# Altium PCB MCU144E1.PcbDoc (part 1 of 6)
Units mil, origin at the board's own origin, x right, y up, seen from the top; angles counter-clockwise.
Board outline 2755.9 x 2276.49 mil, 10 copper layers (Top Layer, L02_GND1, L03_SIG1, L04_GND2, L05_SIG2, L06_PWR, L07_GND3, L08_SIG3, L09_GND4, Bottom Layer), stack 60.4 mil thick; 257 components, 312 nets, 1297 pads, 831 vias.
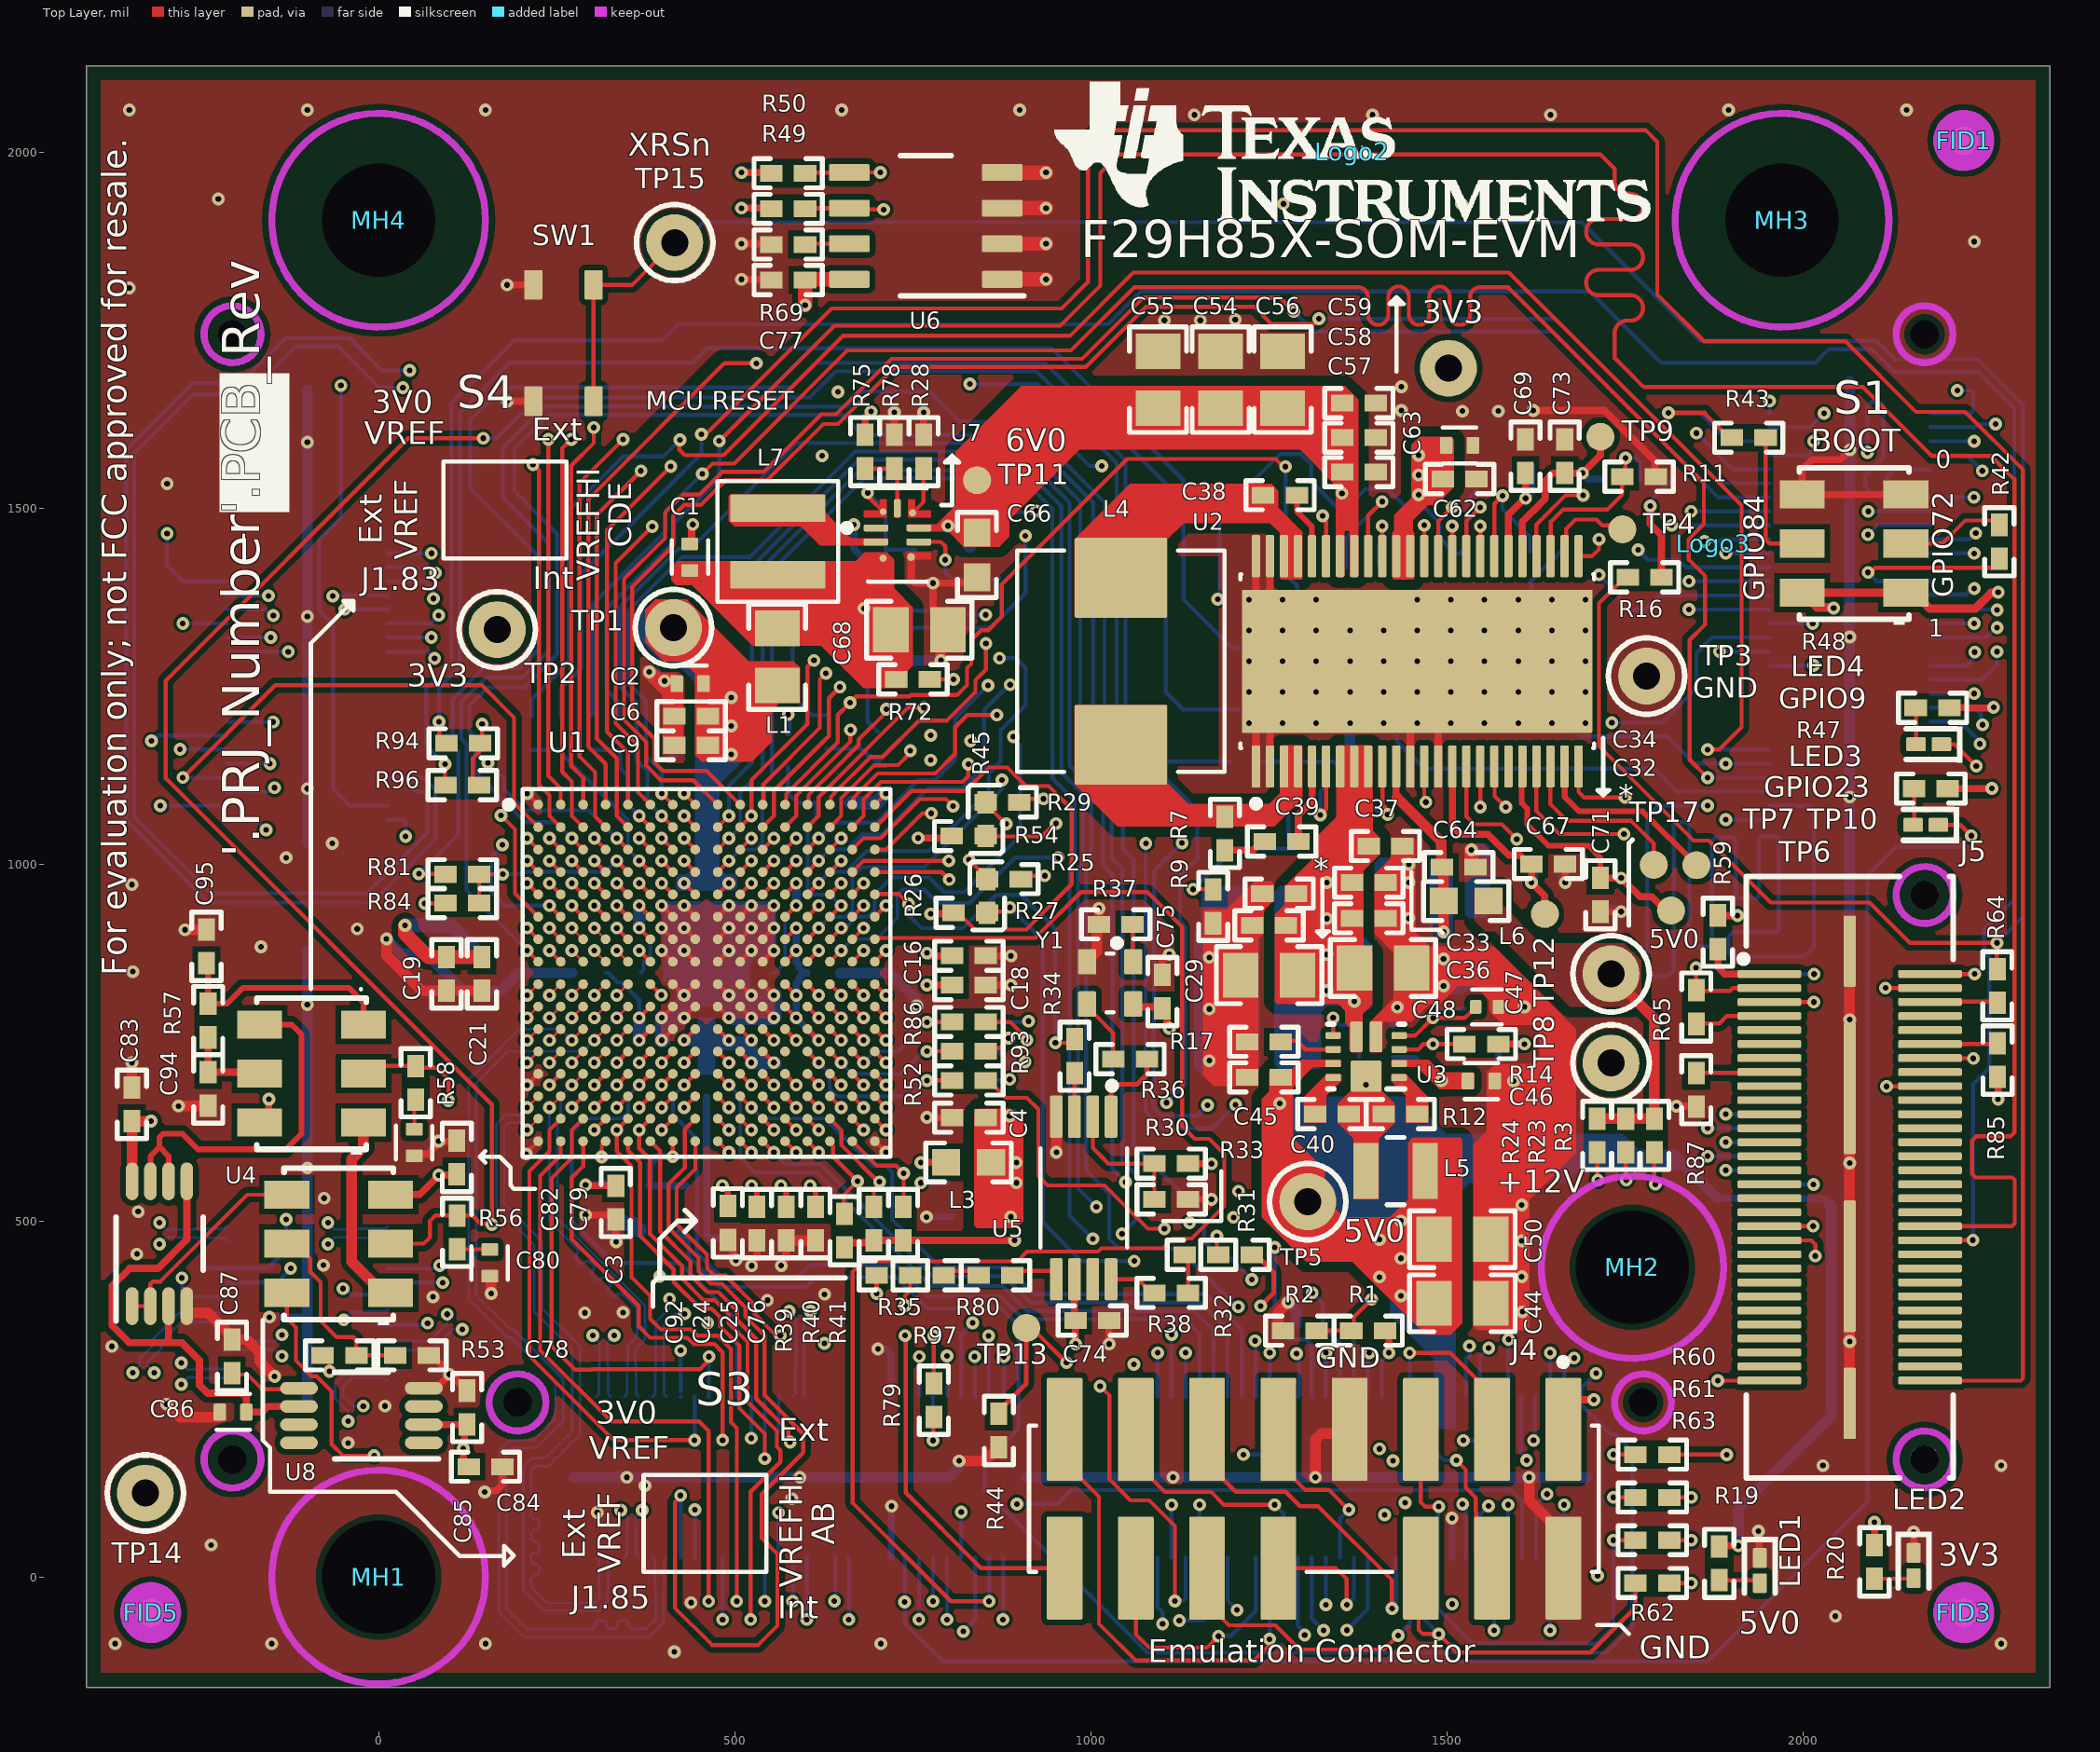
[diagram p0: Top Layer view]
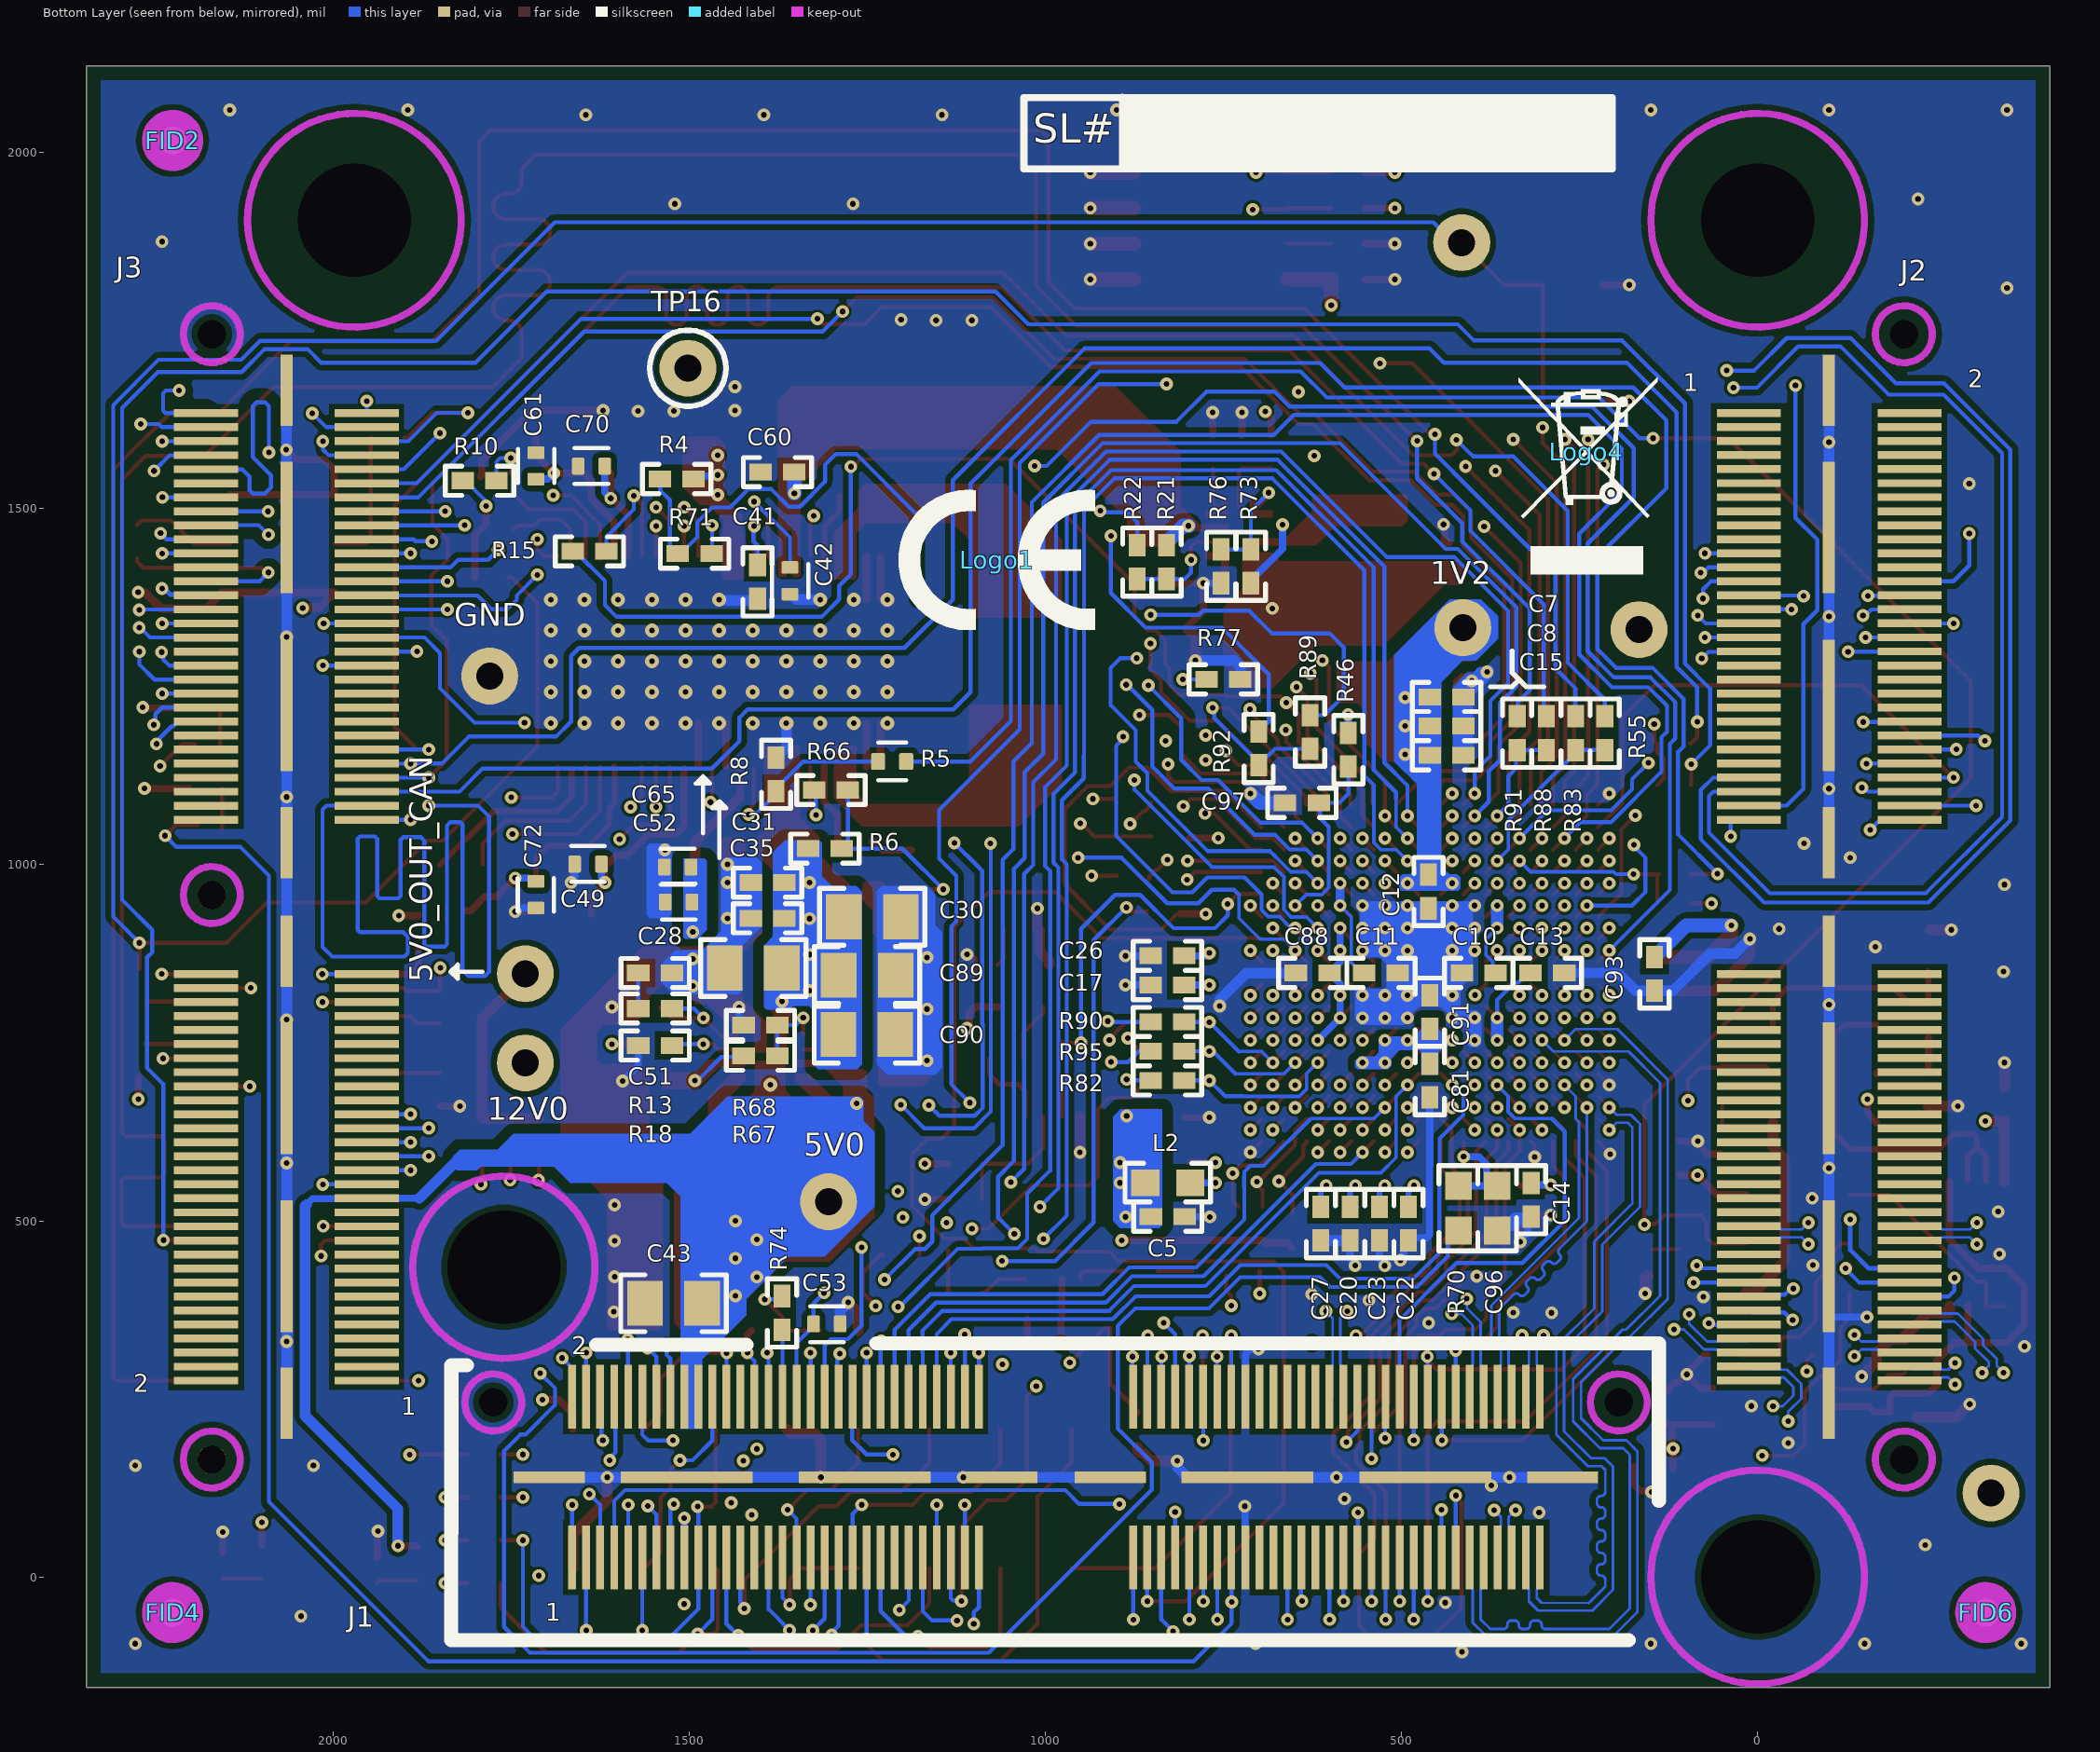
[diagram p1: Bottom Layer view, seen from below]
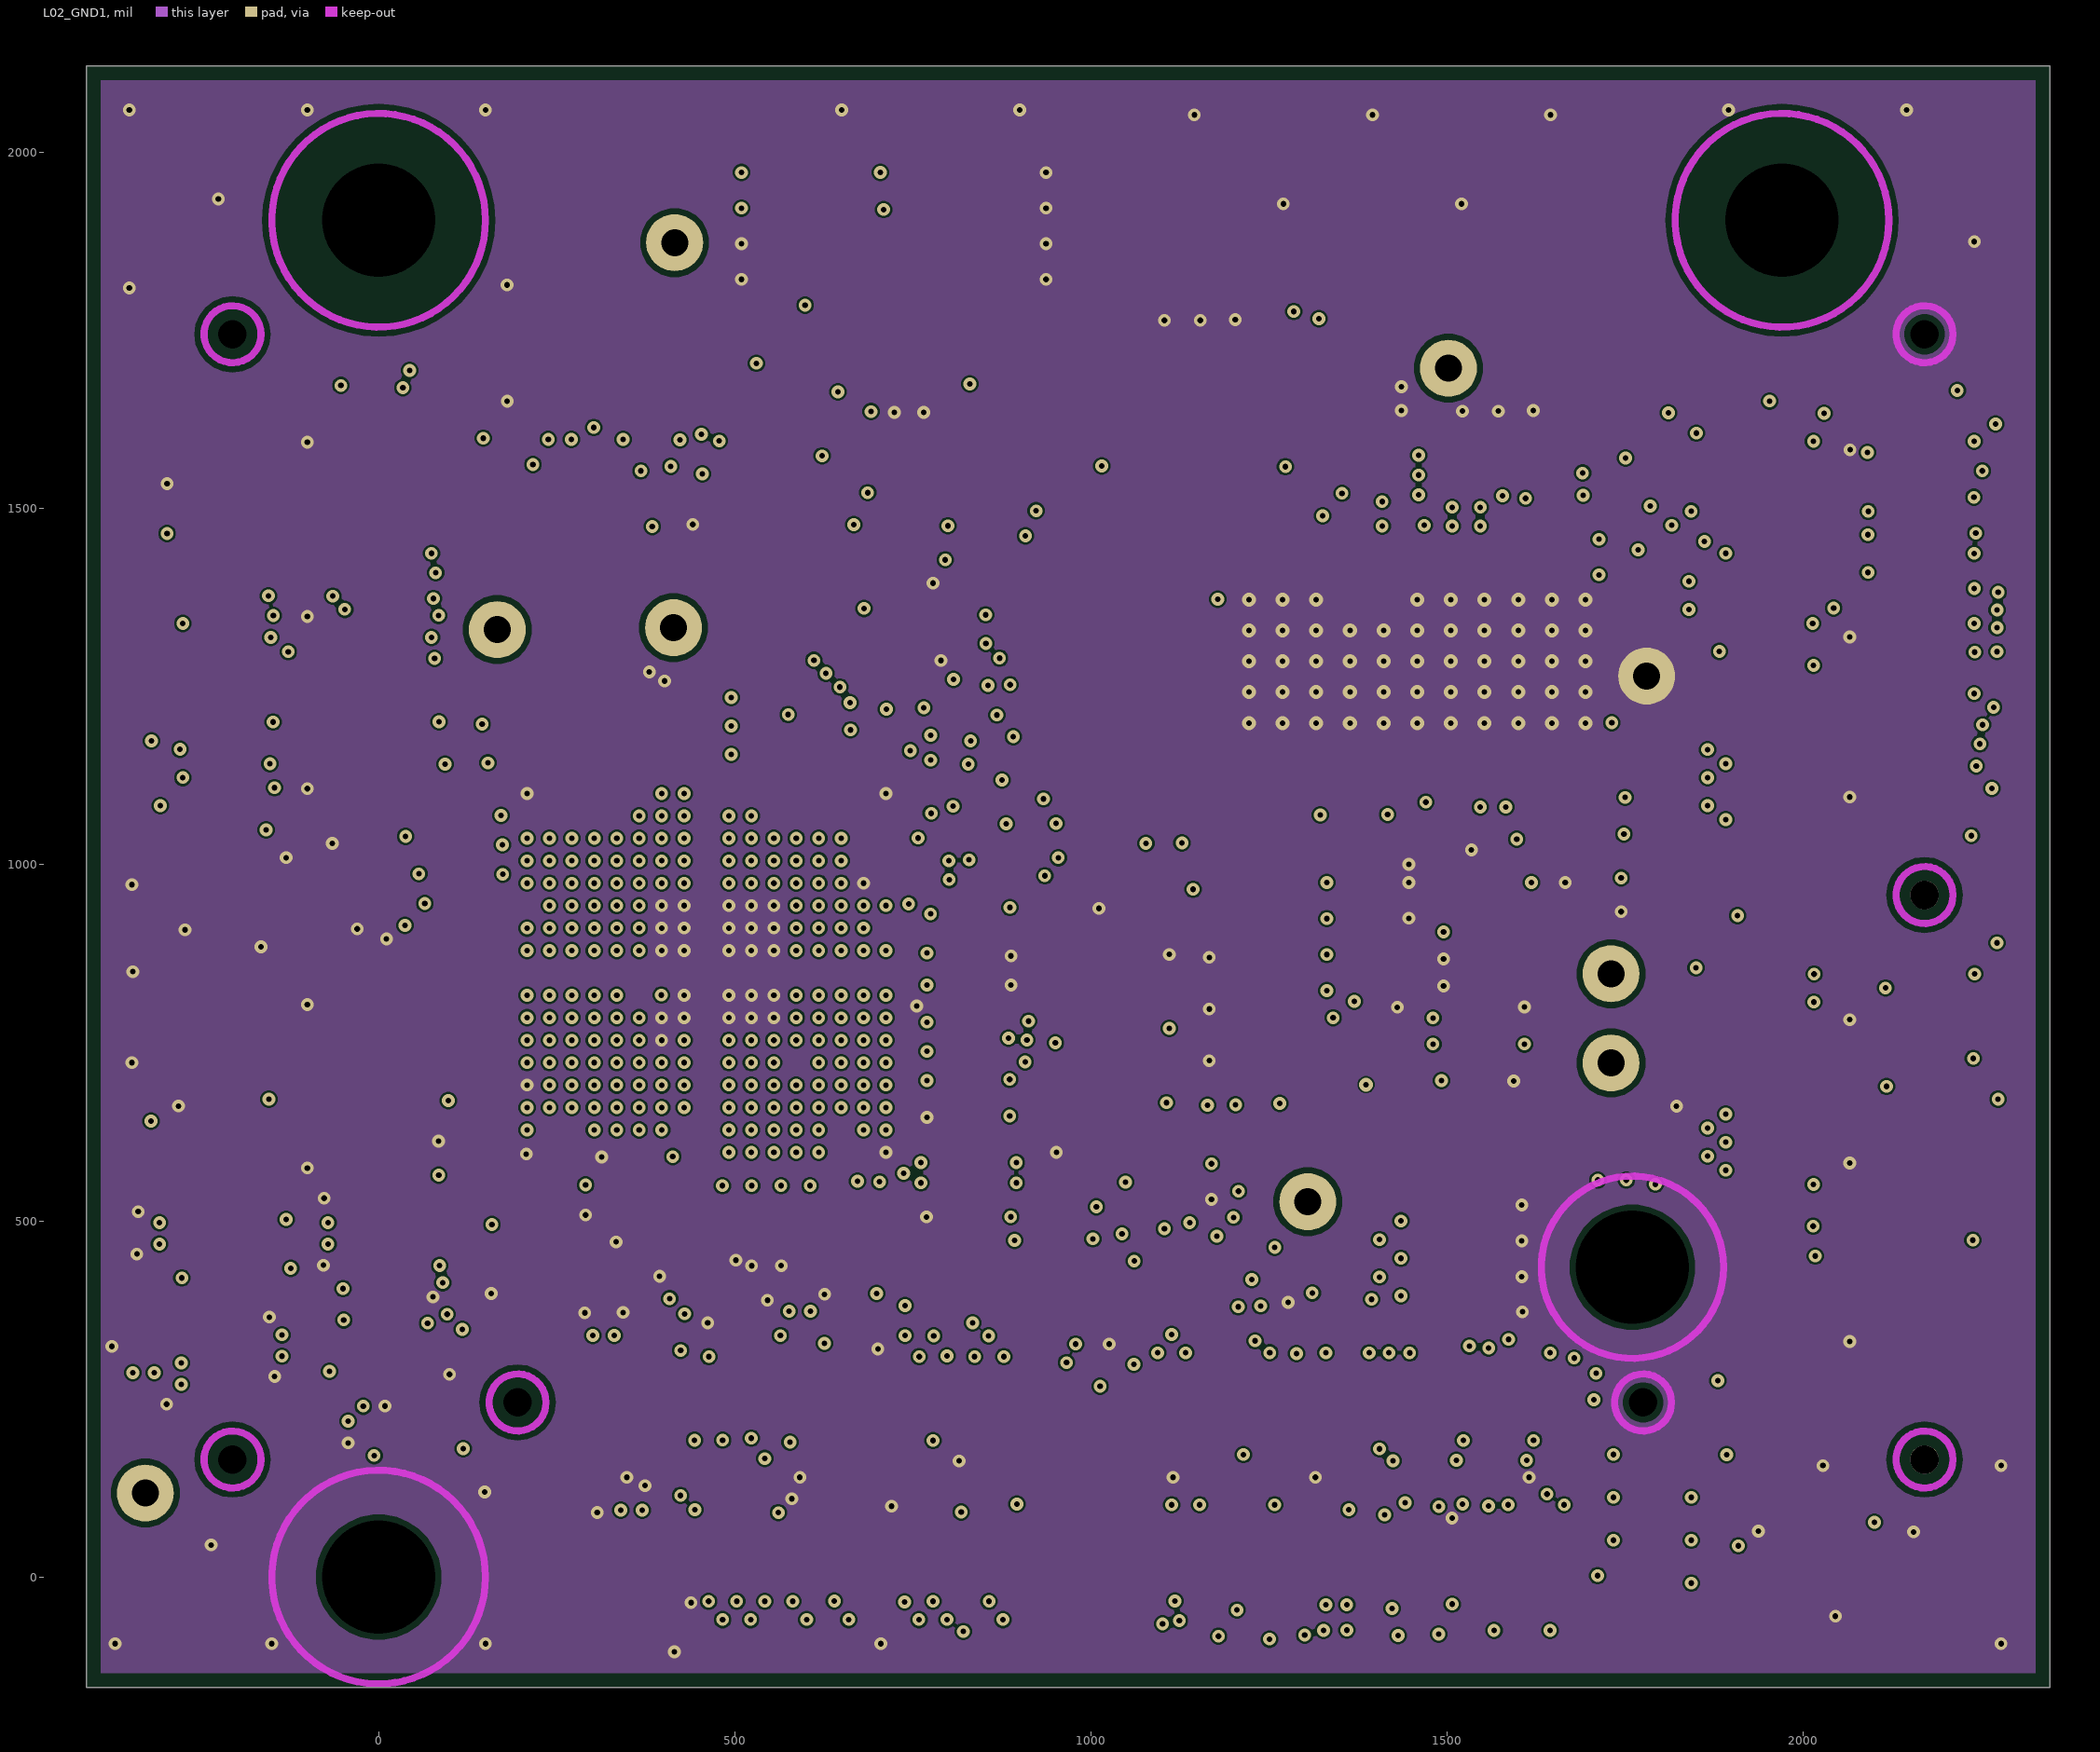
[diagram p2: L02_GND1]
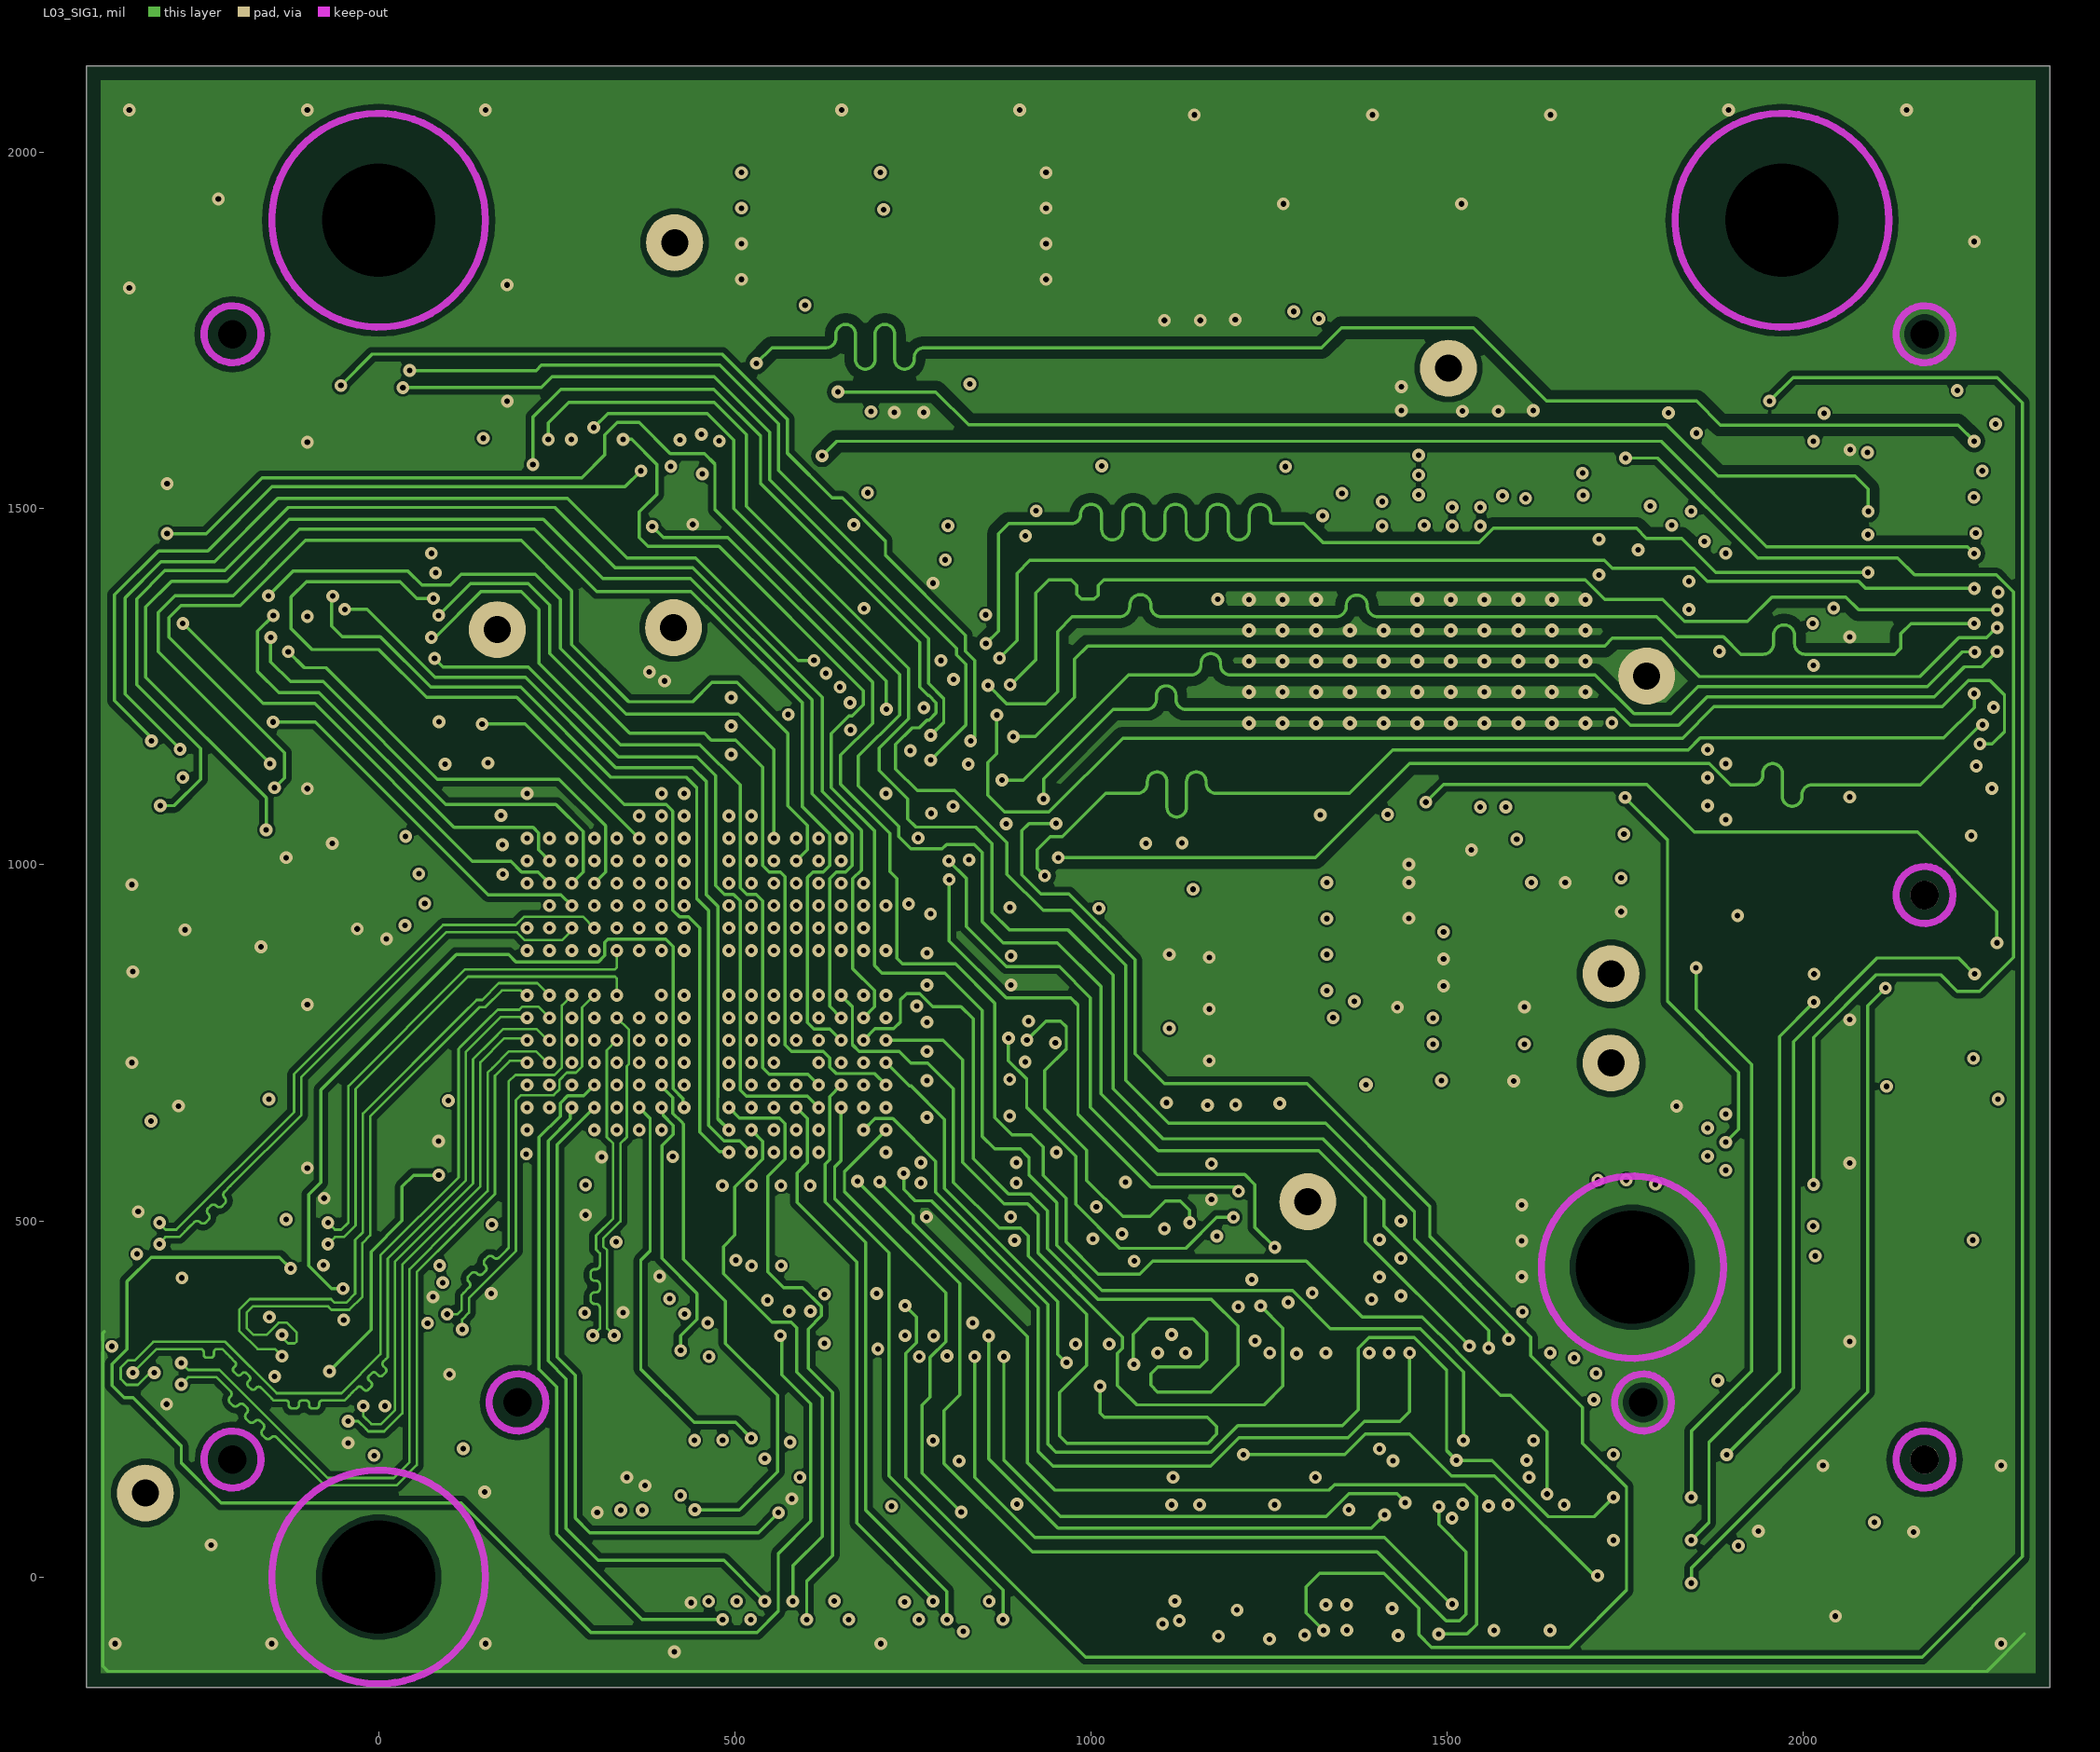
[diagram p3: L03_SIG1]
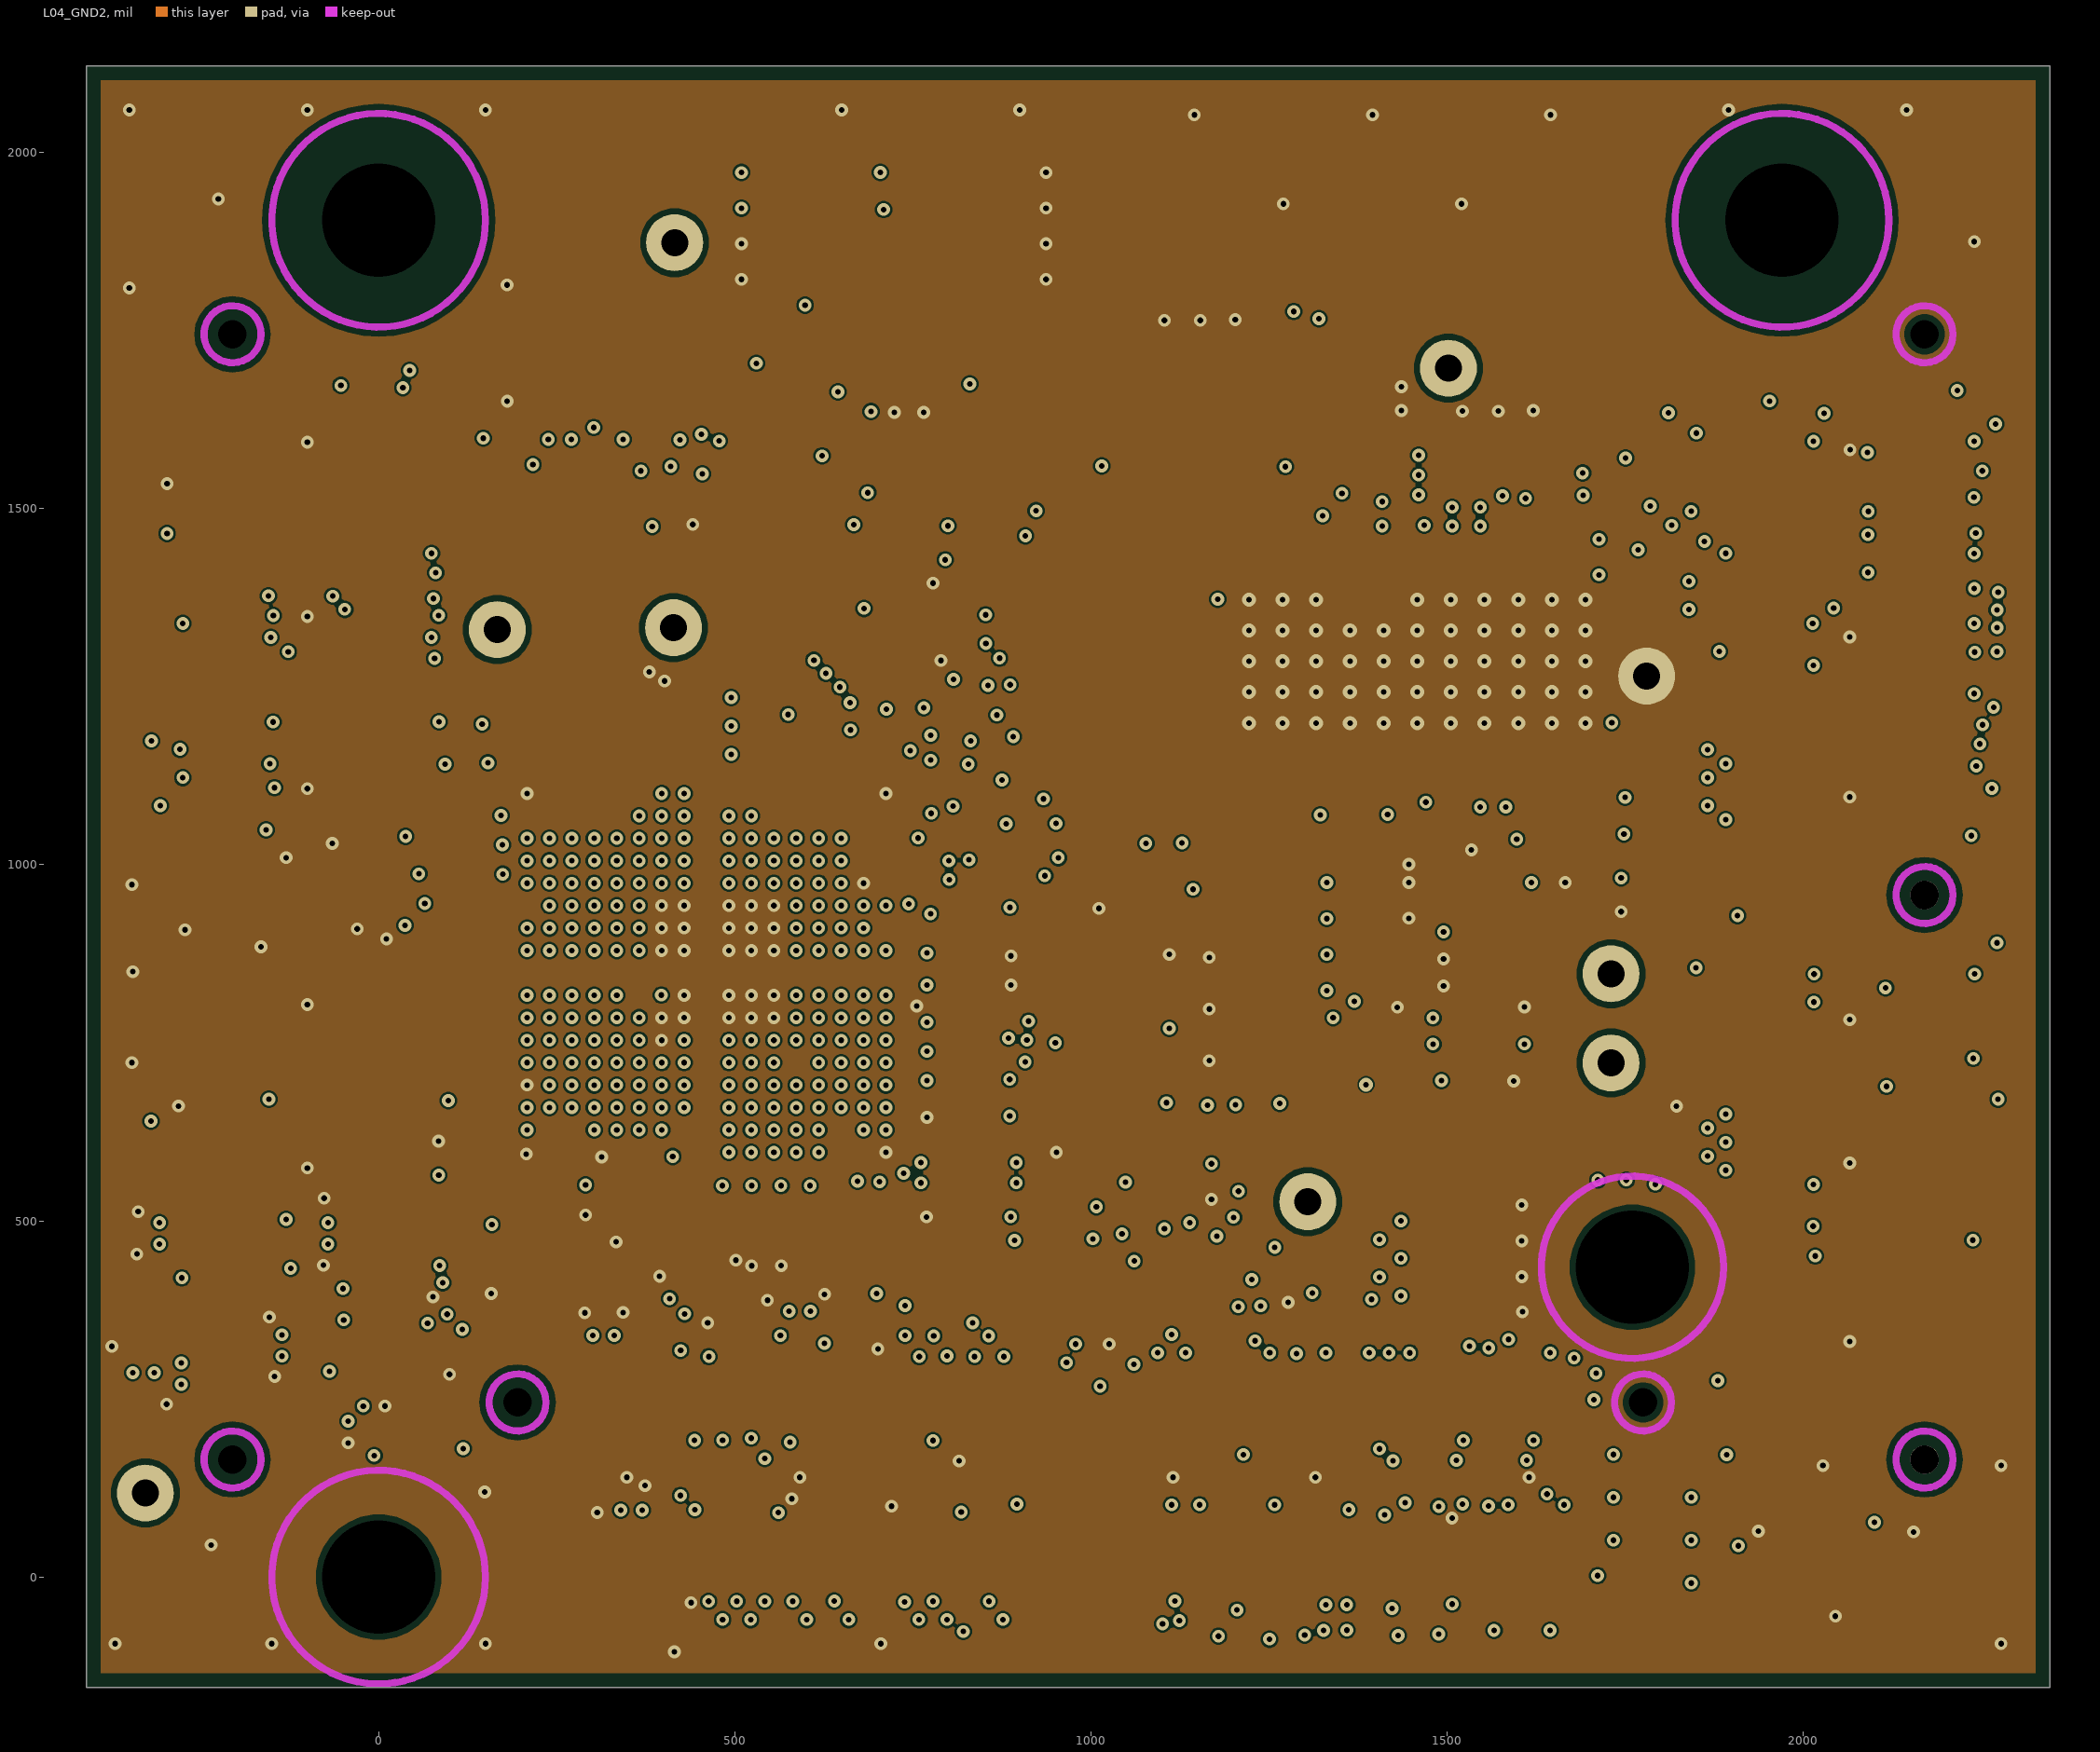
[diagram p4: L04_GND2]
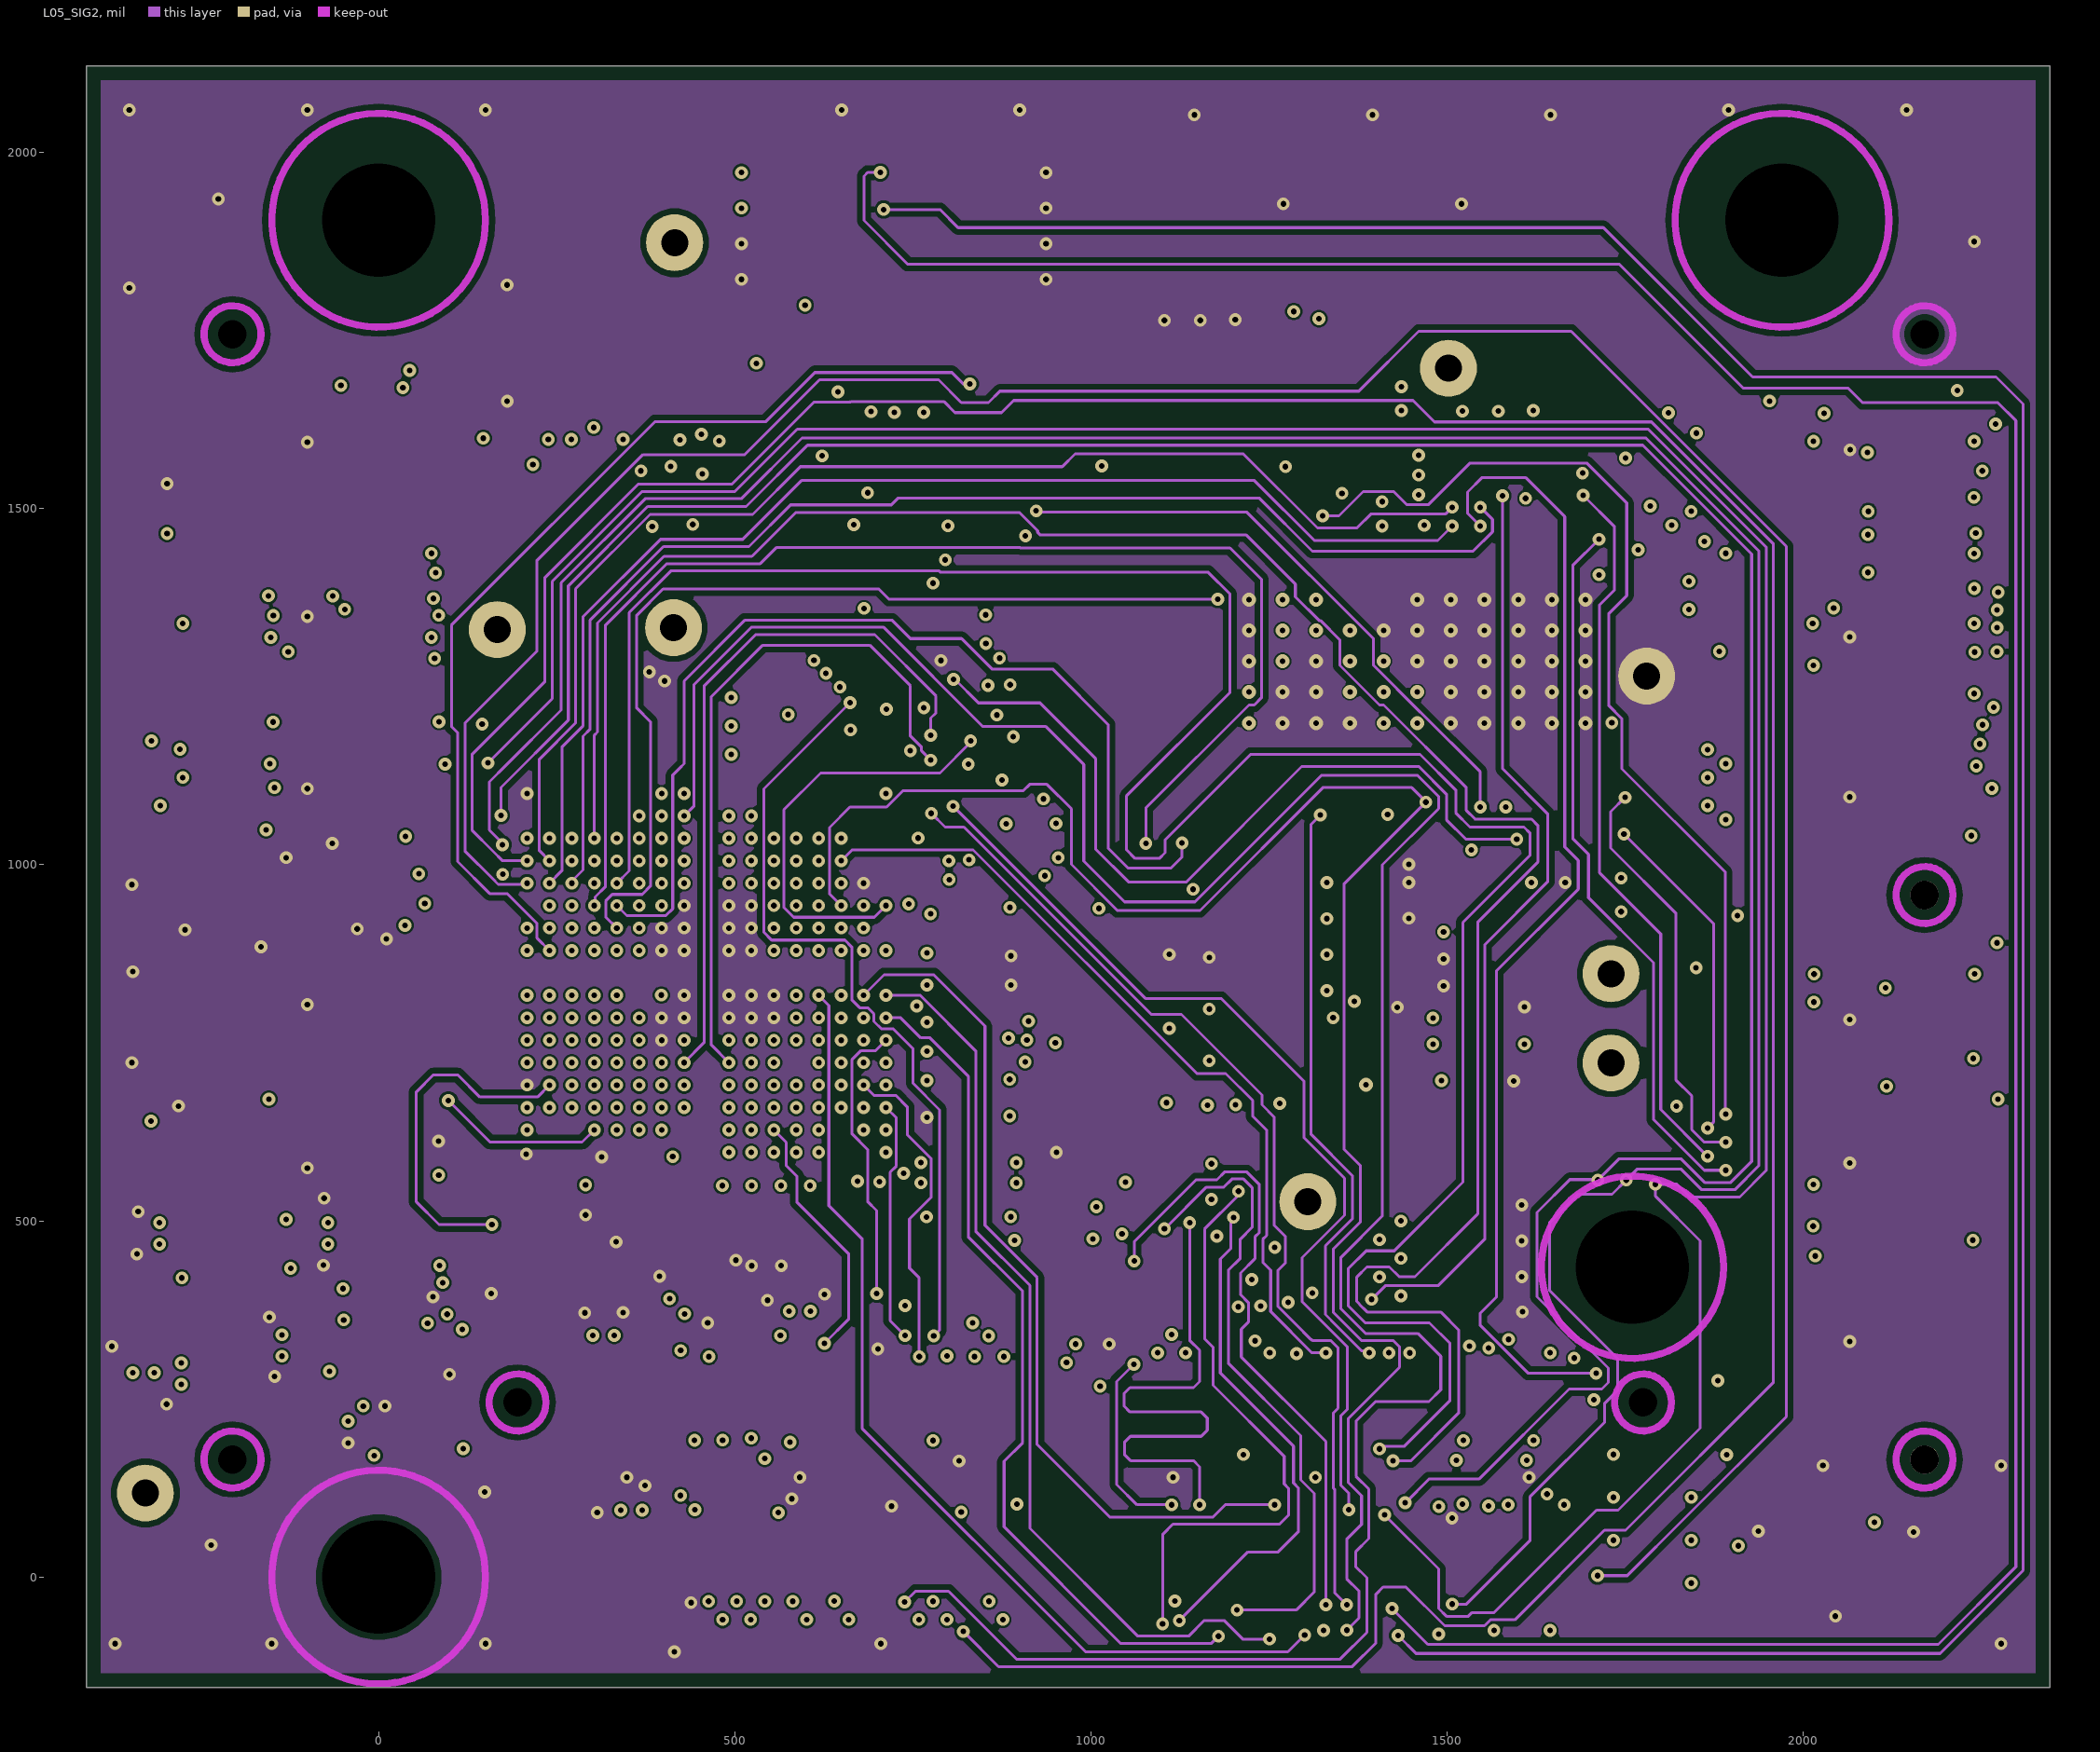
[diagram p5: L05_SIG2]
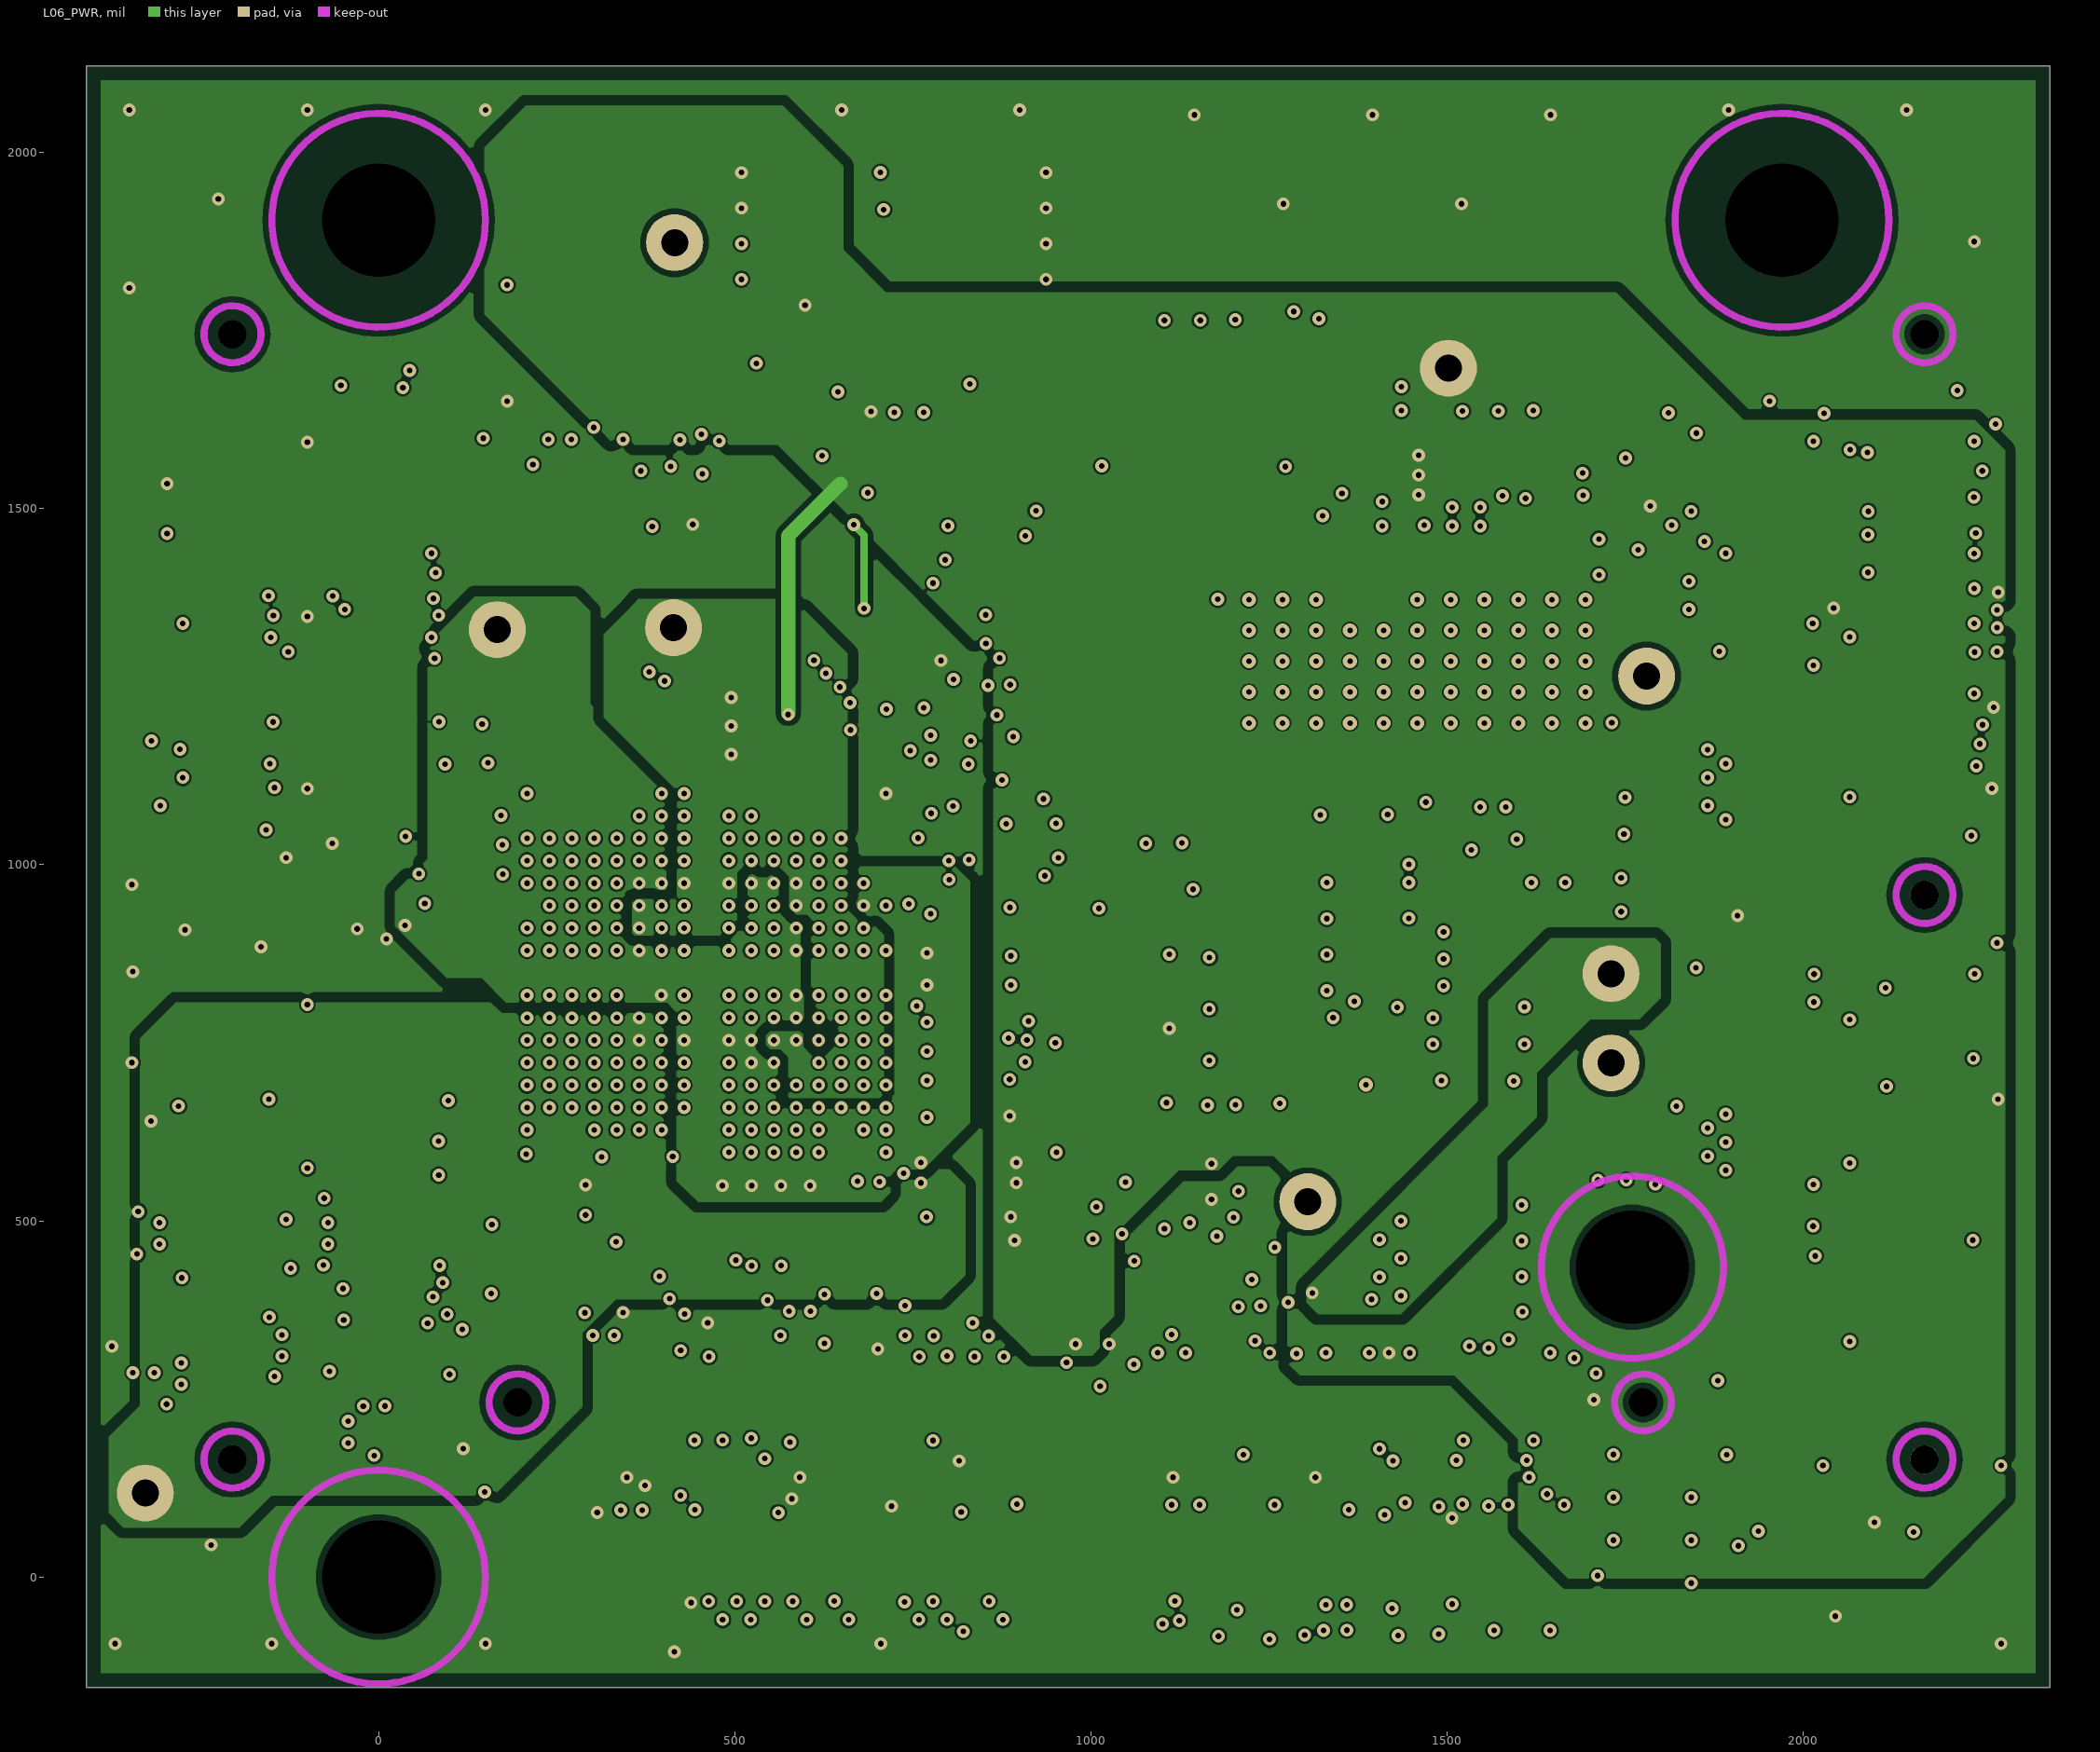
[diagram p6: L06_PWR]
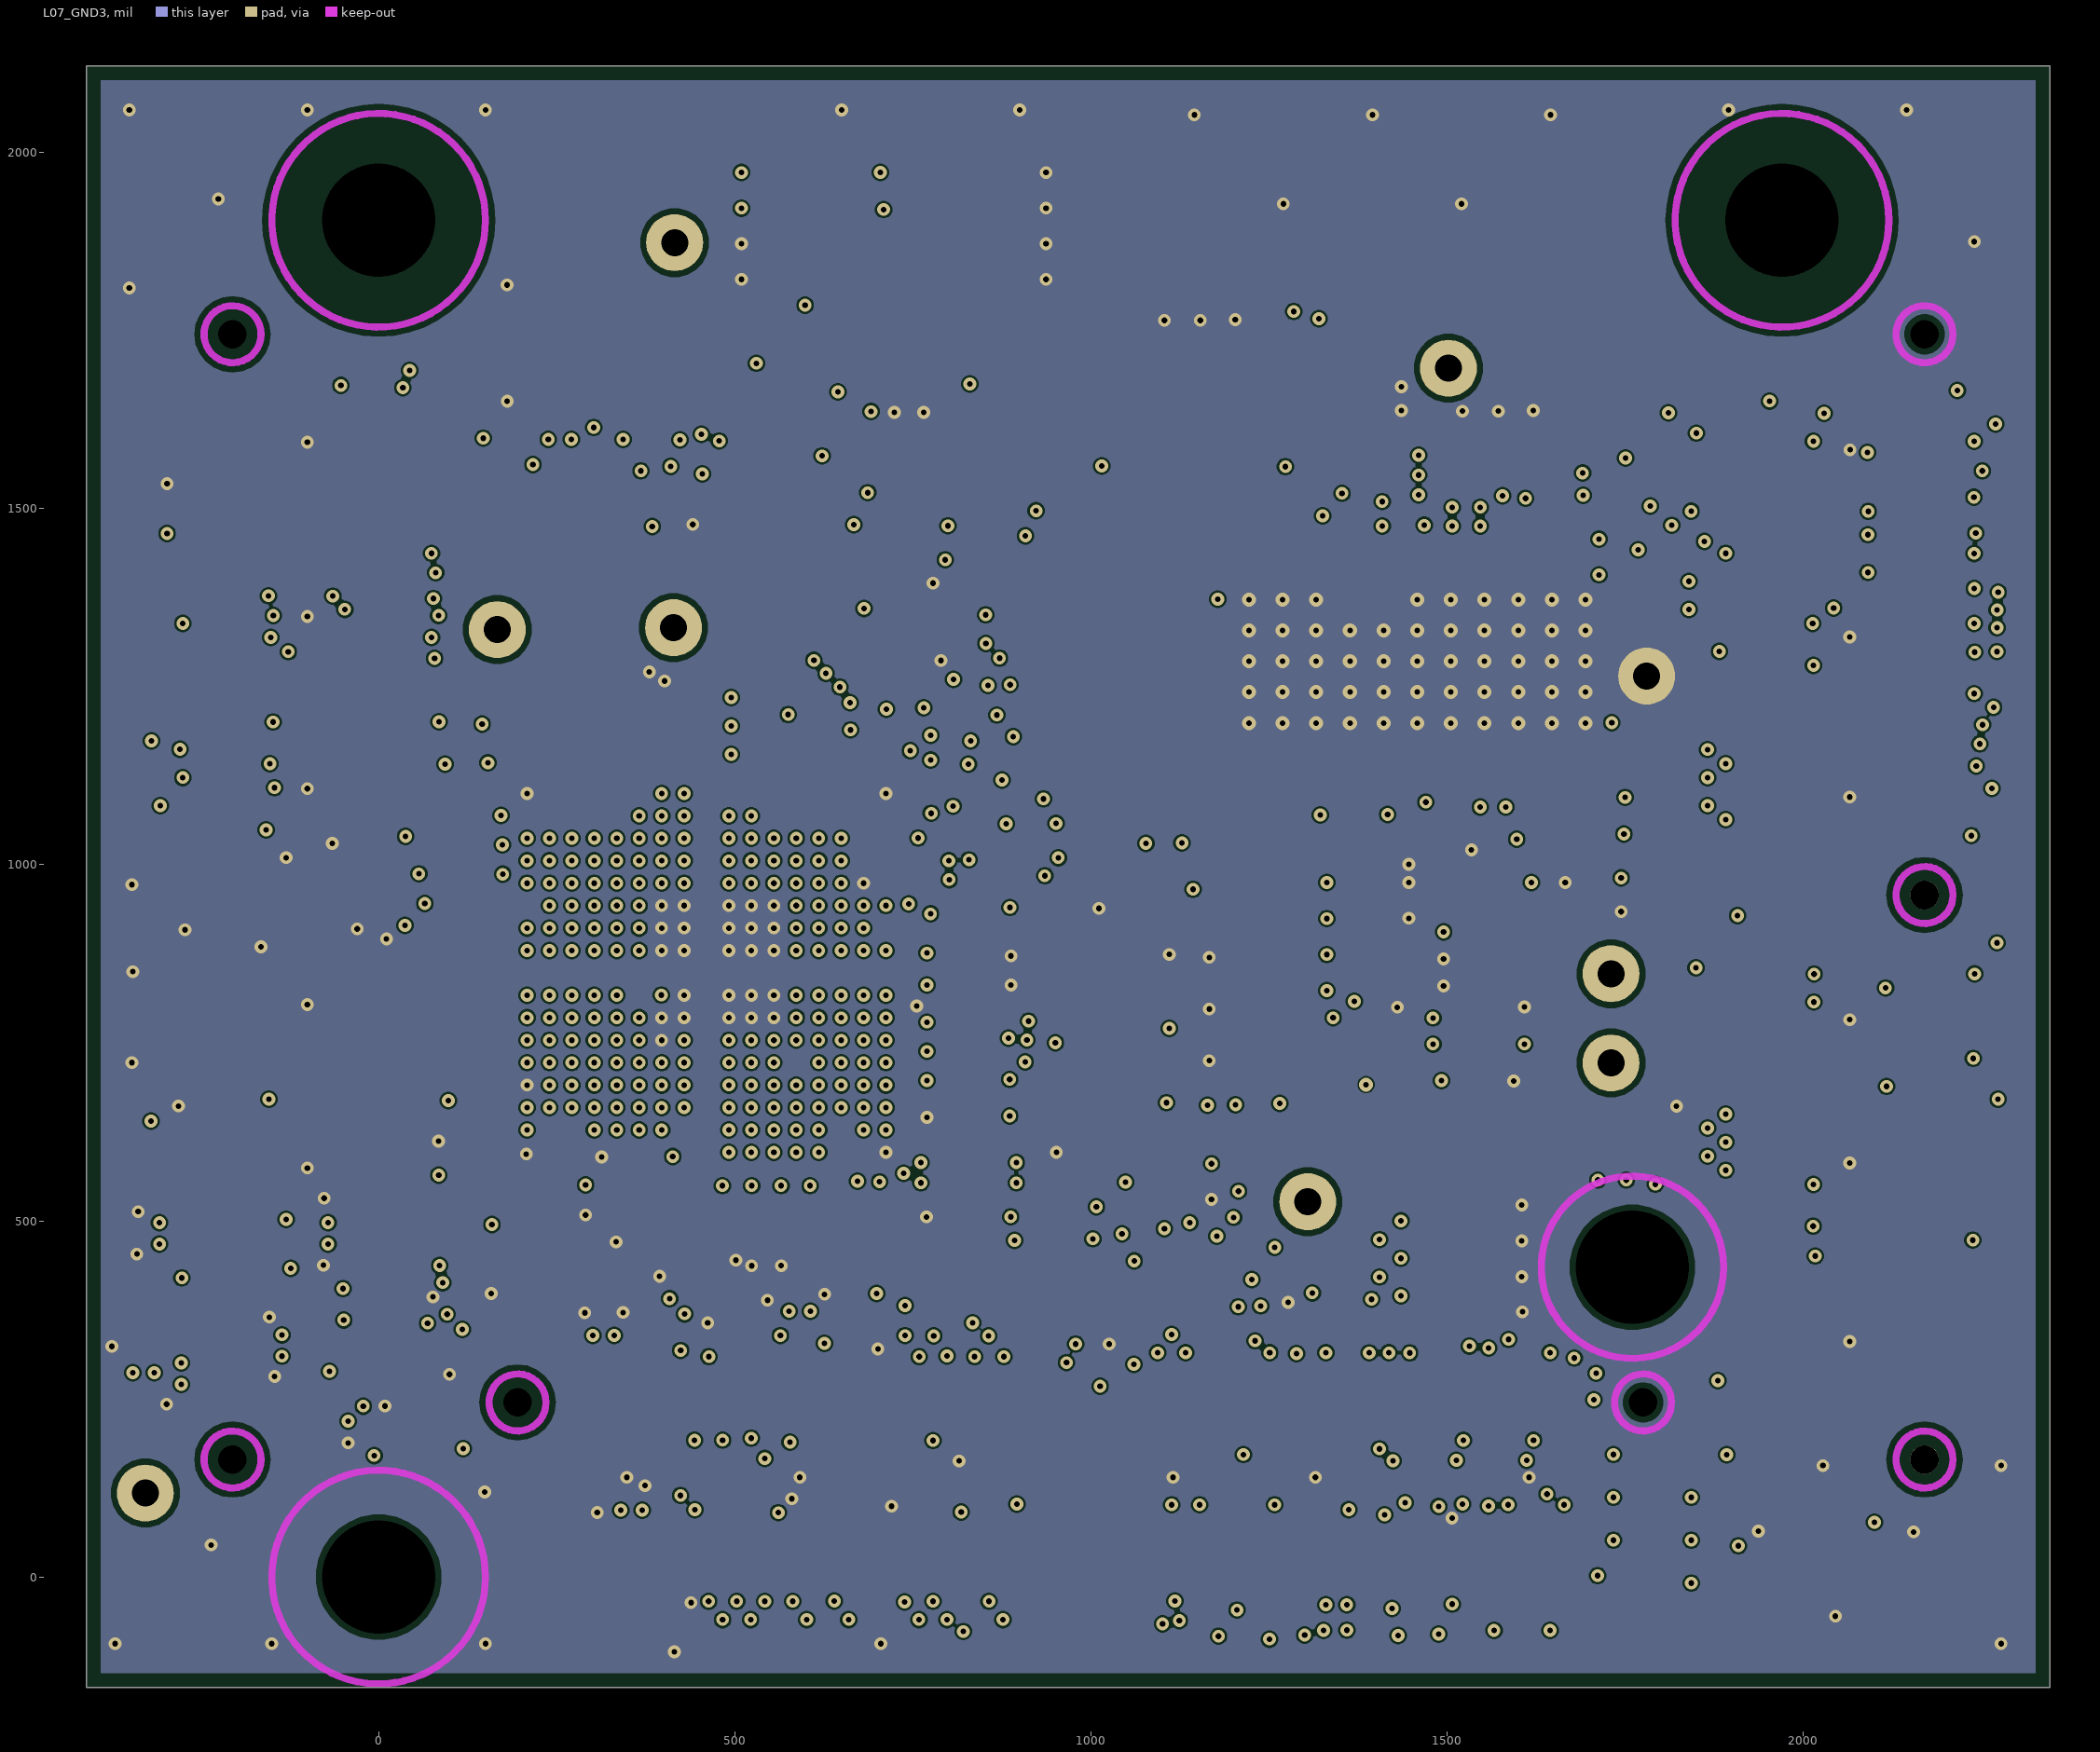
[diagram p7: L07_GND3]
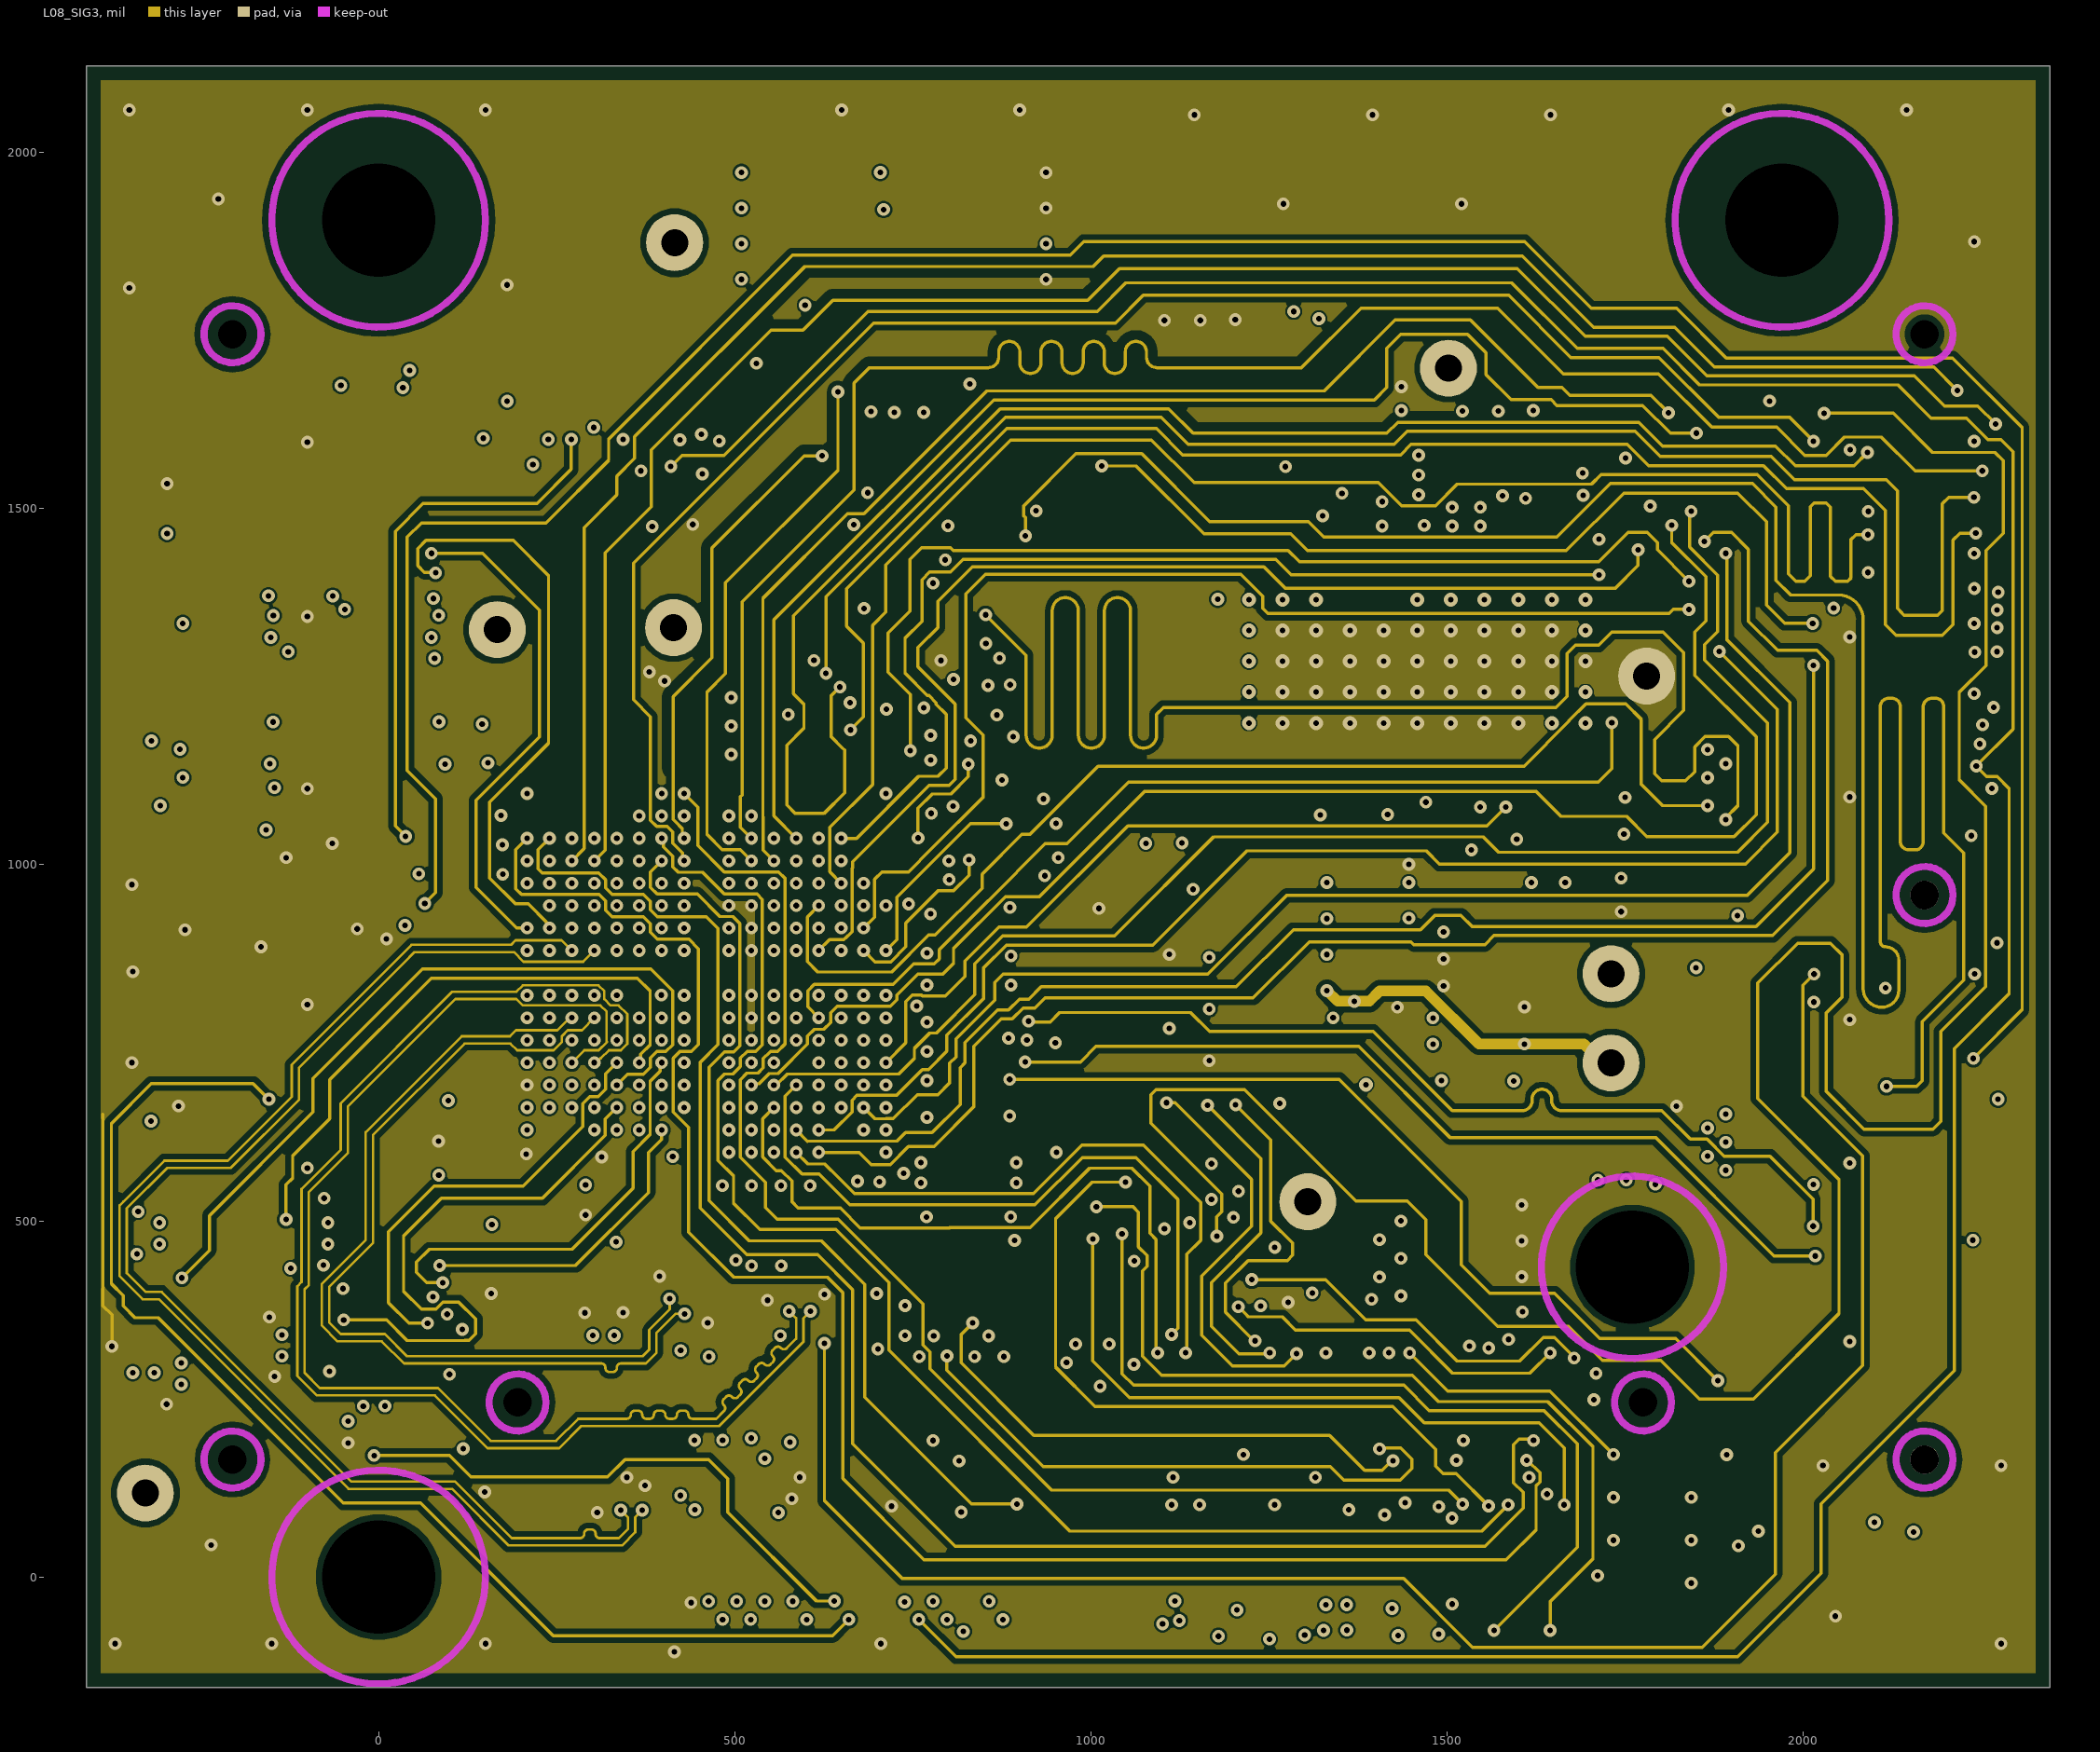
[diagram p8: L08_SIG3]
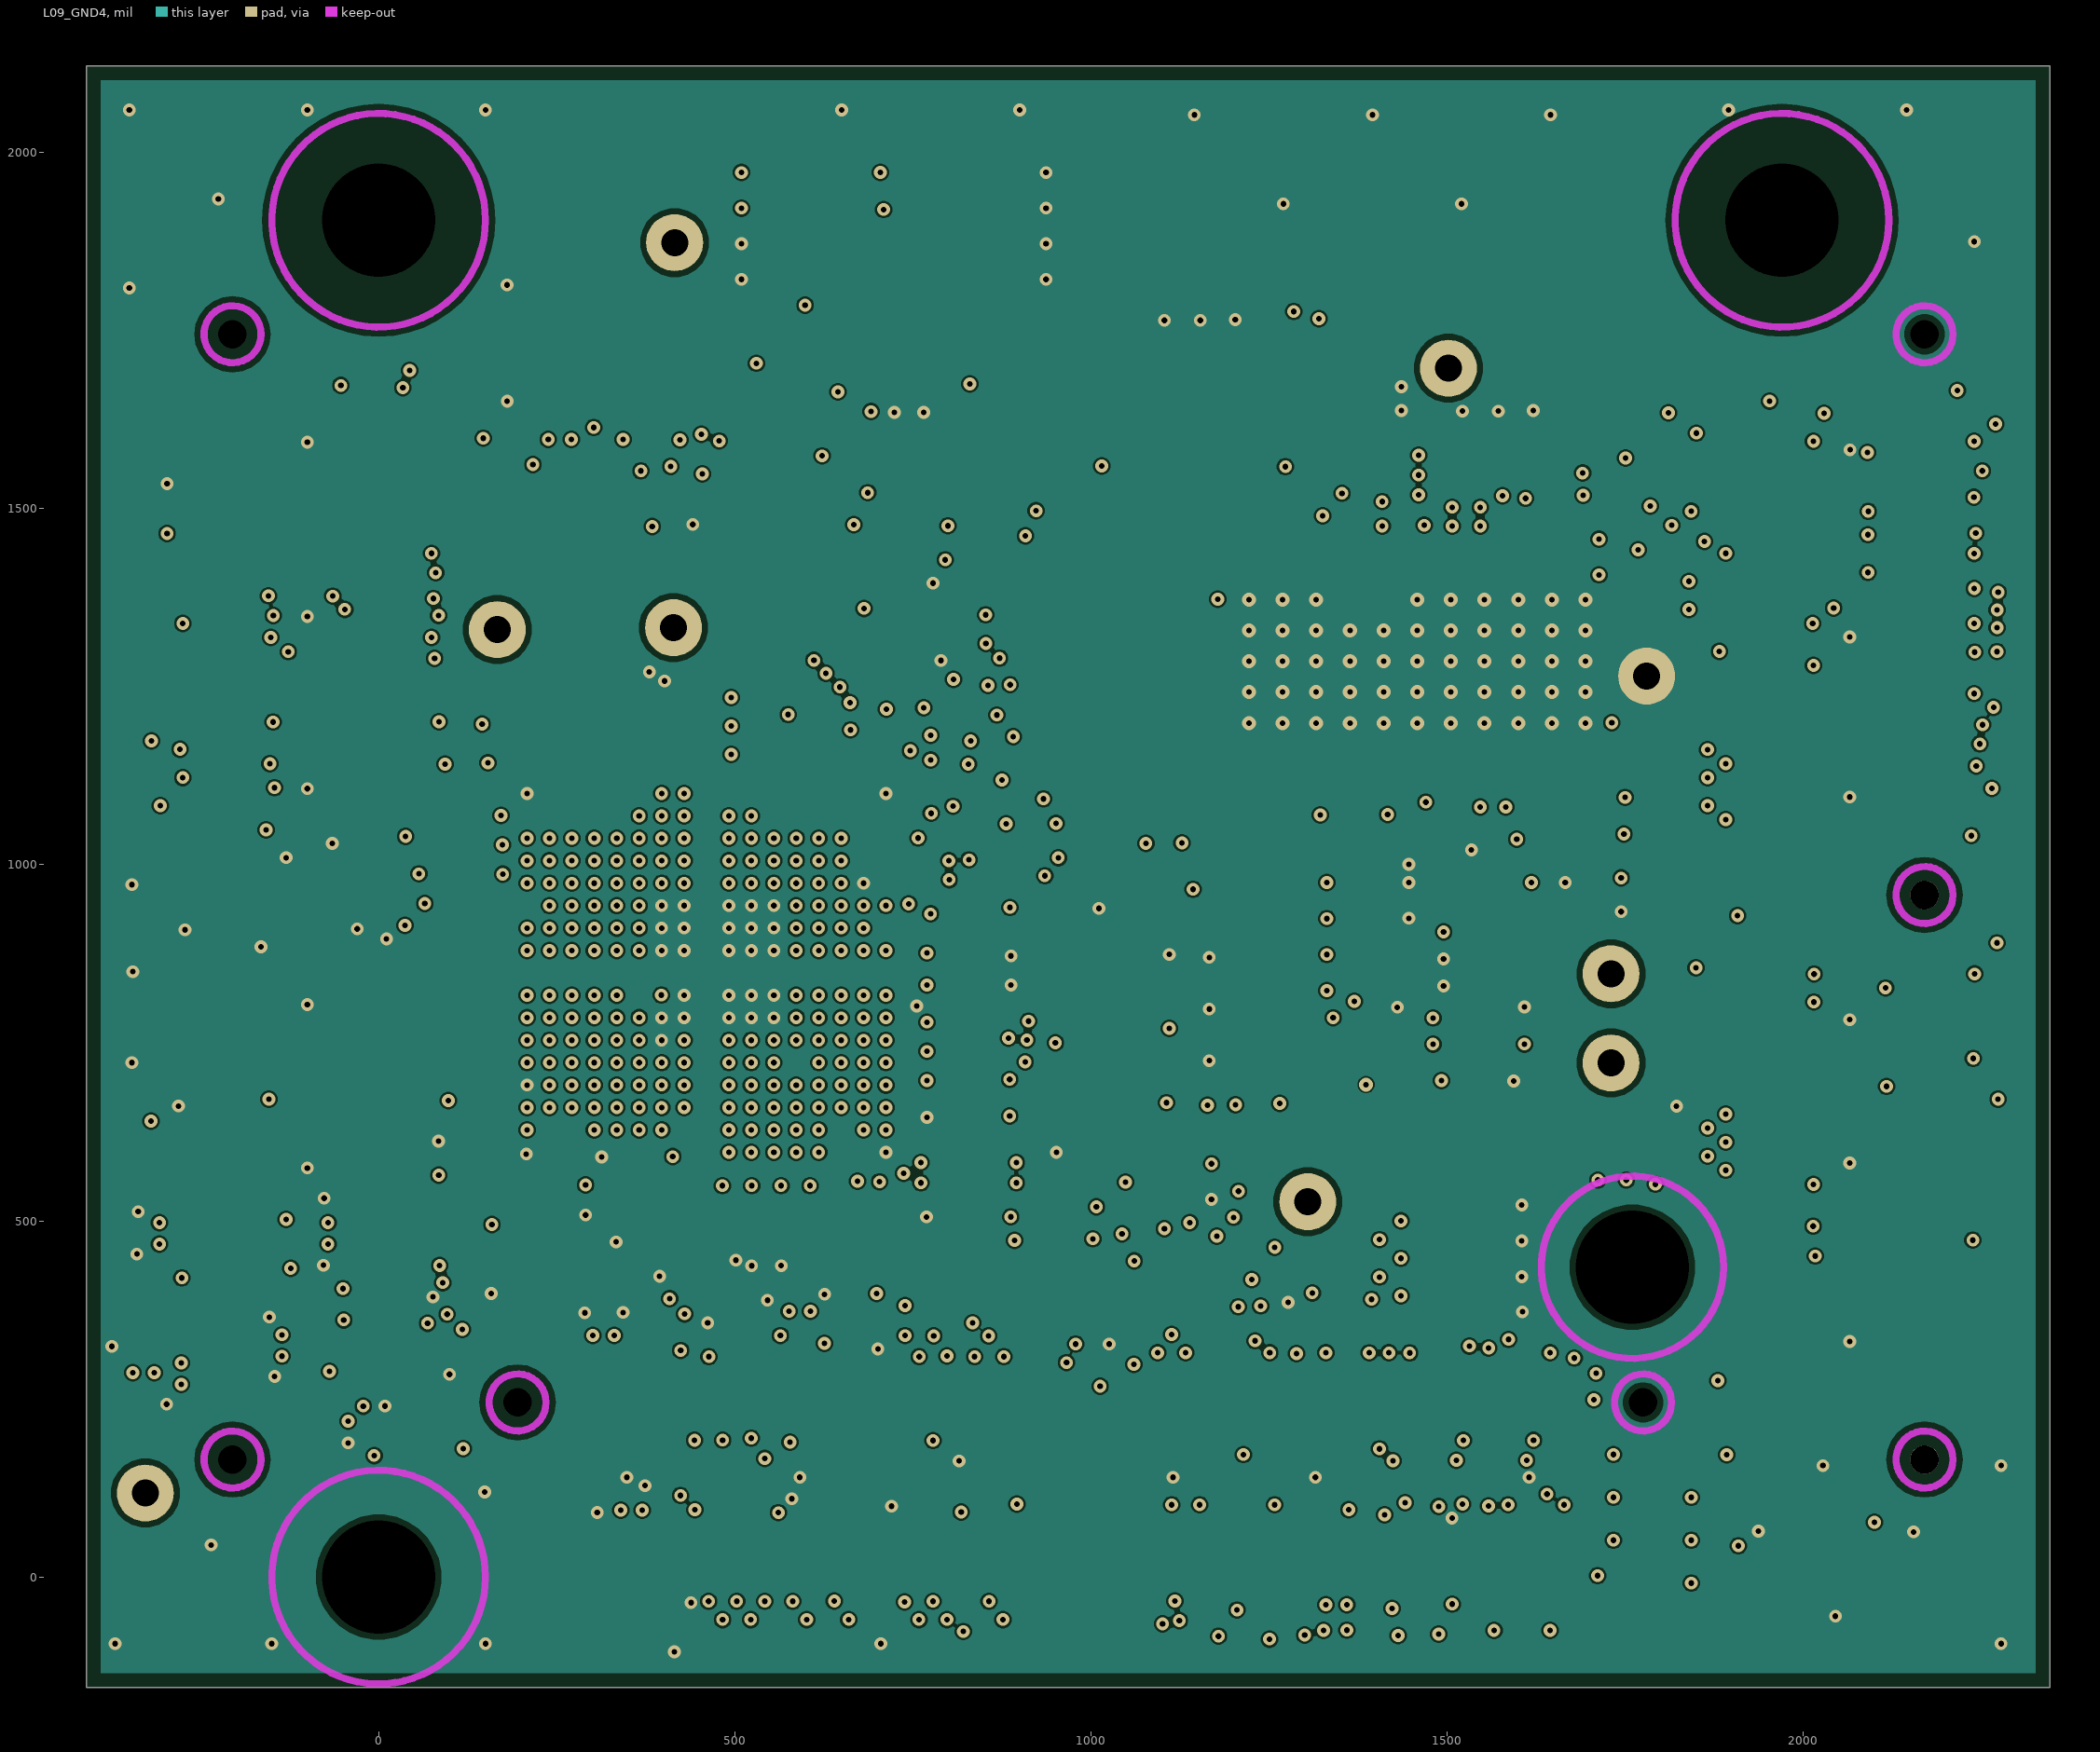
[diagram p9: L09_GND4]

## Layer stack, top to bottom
Top Solder: solder mask 0.5, Solder Resist, Dk 3.5
Top Layer: signal copper 1.4
Dielectric 1: prepreg 3.7, FR-4, Dk 4
L02_GND1: signal copper 1.4
Dielectric 2: core 5, FR-4, Dk 4
L03_SIG1: signal copper 1.4
Dielectric 3: prepreg 7, FR-4, Dk 4
L04_GND2: signal copper 1.4
Dielectric 4: core 4, FR-4, Dk 4
L05_SIG2: signal copper 1.4
Dielectric 5: dielectric 7, FR-4, Dk 4
L06_PWR: signal copper 1.4
Dielectric 6: core 4, FR-4, Dk 4
L07_GND3: signal copper 1.4
Dielectric 7: prepreg 7, FR-4, Dk 4
L08_SIG3: signal copper 1.4
Dielectric 8: core 5, FR-4, Dk 4
L09_GND4: signal copper 1.4
Dielectric 9: prepreg 3.7, FR-4, Dk 4
Bottom Layer: signal copper 1.4
Bottom Solder: solder mask 0.5, Solder Resist, Dk 3.5

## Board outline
-410,-155 2345.9,-155 2345.9,2121.49 -410,2121.49

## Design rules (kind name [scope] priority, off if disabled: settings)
AcuteAngle [All] p1: minimum=4.50000000000000E+0001 checktracksonly=TRUE
BoardOutlineClearance [All] p1: gap=20 ignorepadtopadclearanceinfootprint=FALSE except(0: Arc-SplitContinuation Track-SplitContinuation SMDPad-SplitContinuation THPad-SplitContinuation Via-SplitContinuation Fill-SplitContinuation Poly-SplitContinuation Region-SplitContinuation Text-OutlineEdge Text-SplitContinuation)
Clearance Clearance_FID [IsKeepOut and InComponentClass('FiducialMark') vs IsPad and InComponentClass('FiducialMark')] p1: gap=0 ignorepadtopadclearanceinfootprint=TRUE
Clearance Clearance_BGA_INNERLAYERS [WithinRoom('BGA') vs OnMid] p2: gap=8 ignorepadtopadclearanceinfootprint=TRUE except(2: Text-Text; 4: Arc-Arc Arc-Track Arc-Via Track-Track Track-Via SMDPad-Via THPad-Via Via-Via Via-Fill Via-Poly Via-Region; 5: Arc-SMDPad Track-SMDPad; 10: Fill-Fill Fill-Poly Fill-Region Poly-Poly Poly-Region Region-Region)
Clearance Clearance_BGA_OUTERLAYERS [WithinRoom('BGA') vs OnOutside] p3: gap=8 ignorepadtopadclearanceinfootprint=TRUE except(2: Text-Text; 4: Arc-Via Track-Via Via-Fill Via-Poly Via-Region; 5: Arc-SMDPad Track-SMDPad SMDPad-Via; 6: Arc-Arc Arc-Track Track-Track Via-Via; 10: Fill-Fill Fill-Poly Fill-Region Poly-Poly Poly-Region Region-Region)
Clearance Clearance_DIFF_VIA [All vs InDifferentialPairClass('100OHM')] p4: gap=8 ignorepadtopadclearanceinfootprint=TRUE except(2: Text-Text; 4: Via-Fill Via-Poly Via-Region; 5: Arc-SMDPad Track-SMDPad SMDPad-Via; 6: Arc-Arc Arc-Track Arc-Region Track-Track Track-Via Track-Region SMDPad-Region THPad-Region Fill-Region Region-Region; 7: Arc-Via; 12: Via-Via)
Clearance Clearance_power [InNet('NetC46_2')] p5: gap=8 ignorepadtopadclearanceinfootprint=TRUE except(2: Text-Text; 4: Via-Fill Via-Poly; 5: Arc-SMDPad Arc-THPad Track-SMDPad Track-THPad; 6: Arc-Arc Arc-Track Arc-Region Track-Track Track-Via Track-Region SMDPad-SMDPad SMDPad-Region THPad-Region Via-Via Via-Region Fill-Region Region-Region; 7: Arc-Via SMDPad-Via; 10: Fill-Fill Fill-Poly Poly-Poly Poly-Region)
Clearance Clearance_100E [InDifferentialPairClass('100OHM')] p6: gap=8 ignorepadtopadclearanceinfootprint=TRUE except(2: Text-Text; 4: Arc-Via Track-Via; 5: Arc-SMDPad Track-SMDPad SMDPad-Via; 6: Arc-Arc Arc-Track Arc-Region Track-Track Track-Region SMDPad-SMDPad SMDPad-Region THPad-Region Via-Region Fill-Region Region-Region; 12: Via-Via; 15: Fill-Fill Fill-Poly Poly-Poly Poly-Region)
Clearance Clearance_GND_ETHCAT_Outer [InxSignalClass('RX_0') or InxSignalClass('RX_1') or InxSignalClass('TX_0') or InxSignalClass('TX_1') vs (InNet('GND') and InPolygon) and (OnTopLayer or OnBottomLayer)] p7: gap=8 ignorepadtopadclearanceinfootprint=TRUE except(2: Text-Text; 4: Via-Fill Via-Poly Via-Region; 5: Arc-SMDPad Arc-THPad Track-SMDPad Track-THPad SMDPad-Via; 6: Arc-Arc Arc-Track Track-Track Track-Via Via-Via; 7: Arc-Via; 7.87: SMDPad-Region; 9: Region-Region; 15: Fill-Fill Fill-Poly Fill-Region Poly-Poly Poly-Region; 17: Arc-Poly Track-Poly)
Clearance Clearance_GND_ETHCAT_Inner [InxSignalClass('RX_0') or InxSignalClass('RX_1') or InxSignalClass('TX_0') or InxSignalClass('TX_1') vs InNet('GND') and InPolygon and OnMid] p8: gap=8 ignorepadtopadclearanceinfootprint=TRUE except(2: Text-Text; 4: Via-Fill Via-Poly Via-Region; 5: Arc-SMDPad Arc-THPad Track-SMDPad Track-THPad SMDPad-Via; 6: Arc-Arc Arc-Track Track-Track Track-Via Via-Via; 7: Arc-Via; 7.87: SMDPad-Region; 9: Region-Region; 13.5: Arc-Poly Track-Poly; 15: Fill-Fill Fill-Poly Fill-Region Poly-Poly Poly-Region)
Clearance Clearance_GND [InNet('GND')] p9: gap=8 ignorepadtopadclearanceinfootprint=TRUE except(2: Text-Text; 4: Via-Fill Via-Poly Via-Region; 5: Arc-SMDPad Arc-THPad Track-SMDPad Track-THPad SMDPad-Via; 6: Arc-Arc Arc-Track Track-Track Track-Via Via-Via; 7: Arc-Via; 7.87: SMDPad-Region; 9: Region-Region; 15: Fill-Fill Fill-Poly Fill-Region Poly-Poly Poly-Region)
Clearance [All] p10: gap=8 ignorepadtopadclearanceinfootprint=TRUE except(2: Text-Text; 5: Arc-SMDPad Arc-THPad Track-SMDPad Track-THPad SMDPad-Via; 6: Arc-Arc Arc-Track Arc-Via Track-Track Track-Via Via-Via; 7: Via-Fill Via-Poly Via-Region; 7.87: SMDPad-Poly SMDPad-Region; 9: Region-Region; 15: Fill-Fill Fill-Poly Fill-Region Poly-Poly Poly-Region)
ComponentClearance ComponentClearance_1 [InComponent('R45') vs InComponent('R29') or InComponent('R54')] p1: gap=0 collisioncheckmode=3 verticalgap=0 showdistances=FALSE
ComponentClearance ComponentClearance_2 [InComponent('R26') vs InComponent('R25') or InComponent('R27')] p2: gap=0 collisioncheckmode=3 verticalgap=0 showdistances=FALSE
ComponentClearance ComponentClearance_3 [InComponent('R97') vs InComponent('R35') or InComponent('R80')] p3: gap=0 collisioncheckmode=3 verticalgap=0 showdistances=FALSE
ComponentClearance ComponentClearance_4 [InComponent('R31') vs InComponent('R32')] p4: gap=0 collisioncheckmode=3 verticalgap=0 showdistances=FALSE
ComponentClearance [All] p5: gap=10 collisioncheckmode=3 verticalgap=10 showdistances=FALSE
DiffPairsRouting [InDifferentialPairClass('100OHM')] p1: maxlimit=10 minlimit=6.7 mostfreqgap=10 toplayer_mingap=7.3 toplayer_maxgap=7.3 toplayer_prefgap=7.3 toplayer_minwidth=3.7 toplayer_maxwidth=3.7 toplayer_prefwidth=3.7 midlayer1_mingap=10 midlayer1_minwidth=15 midlayer1_maxwidth=15 midlayer1_prefwidth=15 midlayer2_maxgap=6.7 midlayer2_prefgap=6.7 midlayer2_minwidth=3.5 midlayer2_maxwidth=3.5 midlayer2_prefwidth=3.5 midlayer3_mingap=10 midlayer3_minwidth=15 midlayer3_maxwidth=15 midlayer3_prefwidth=15 midlayer4_mingap=10 midlayer4_minwidth=15 midlayer4_maxwidth=15 midlayer4_prefwidth=15 midlayer5_mingap=7.3 midlayer5_maxgap=7.3 midlayer5_prefgap=7.3 midlayer5_minwidth=3.5 midlayer5_maxwidth=3.5 midlayer5_prefwidth=3.5 midlayer6_mingap=10 midlayer6_minwidth=15 midlayer6_maxwidth=15 midlayer6_prefwidth=15 midlayer7_mingap=10 midlayer7_minwidth=15 midlayer7_maxwidth=15 midlayer7_prefwidth=15 midlayer8_mingap=10 midlayer8_minwidth=15 midlayer8_maxwidth=15 midlayer8_prefwidth=15 bottomlayer_mingap=7.3 bottomlayer_maxgap=7.3 bottomlayer_prefgap=7.3 bottomlayer_minwidth=3.7 bottomlayer_maxwidth=3.7 bottomlayer_prefwidth=3.7 maxuncoupledlength=2000
HoleSize [All] p1: absolutevalues=TRUE maxlimit=200 minlimit=1 maxpercent=80.000 minpercent=20.000
HoleToHoleClearance [InComponent('J3')] p1: gap=0 allowstackedmicrovias=FALSE
MatchedLengths MatchedLengths_FSIRXA_SOM [InxSignalClass('FSIRXA_SOM')] p1: tolerance=35 checknetsindiffpair=FALSE checkdiffpairvsdiffpair=TRUE checkxsignals=TRUE checkothers=TRUE
MatchedLengths MatchedLengths_FSIRXC_DLT [InxSignalClass('FSIRXC_DLT')] p2: tolerance=35 checknetsindiffpair=FALSE checkdiffpairvsdiffpair=TRUE checkxsignals=TRUE checkothers=TRUE
MatchedLengths MatchedLengths_FSITXB_DLT [InxSignalClass('FSITXB_DLT')] p3: tolerance=35 checknetsindiffpair=FALSE checkdiffpairvsdiffpair=TRUE checkxsignals=TRUE checkothers=TRUE
MatchedLengths MatchedLengths_FSITXA_DLT_1 [InxSignalClass('FSITXA_DLT')] p4: tolerance=35 checknetsindiffpair=FALSE checkdiffpairvsdiffpair=TRUE checkxsignals=TRUE checkothers=TRUE
MatchedLengths MatchedLengths_FSIRXC_SOM [InxSignalClass('FSIRXC_SOM')] p5: tolerance=35 checknetsindiffpair=FALSE checkdiffpairvsdiffpair=TRUE checkxsignals=TRUE checkothers=TRUE
MatchedLengths MatchedLengths_FSITXB_SOM [InxSignalClass('FSITXB_SOM')] p6: tolerance=35 checknetsindiffpair=FALSE checkdiffpairvsdiffpair=TRUE checkxsignals=TRUE checkothers=TRUE
MatchedLengths MatchedLengths_FSITXA_SOM [InxSignalClass('FSITXA_SOM')] p7: tolerance=35 checknetsindiffpair=FALSE checkdiffpairvsdiffpair=TRUE checkxsignals=TRUE checkothers=TRUE
MatchedLengths MatchedLengths_TX0 [InxSignalClass('TX_0')] p8: tolerance=25 checknetsindiffpair=FALSE checkdiffpairvsdiffpair=TRUE checkxsignals=TRUE checkothers=TRUE
MatchedLengths MatchedLengths_RX0 [InxSignalClass('RX_0')] p9: tolerance=25 checknetsindiffpair=FALSE checkdiffpairvsdiffpair=TRUE checkxsignals=TRUE checkothers=TRUE
MatchedLengths MatchedLengths_RX1 [InxSignalClass('RX_1')] p10: tolerance=25 checknetsindiffpair=FALSE checkdiffpairvsdiffpair=TRUE checkxsignals=TRUE checkothers=TRUE
MatchedLengths MatchedLengths_TX1 [InxSignalClass('TX_1')] p11: tolerance=25 checknetsindiffpair=FALSE checkdiffpairvsdiffpair=TRUE checkxsignals=TRUE checkothers=TRUE
MatchedLengths [InDifferentialPairClass('100OHM')] p12: tolerance=5 checknetsindiffpair=TRUE checkdiffpairvsdiffpair=FALSE checkxsignals=FALSE checkothers=FALSE
MinimumAnnularRing [All] p1: minimumring=5
MinimumSolderMaskSliver MinimumSolderMaskSliver_exception [HasFootprint('CONN_QSH-060-01-L-D-A')] p1: minsoldermaskwidth=3.94
MinimumSolderMaskSliver [All] p2: minsoldermaskwidth=3.94
PolygonConnect [All] p1: connectstyle=Direct reliefconductorwidth=10 reliefentries=4 polygonreliefangle="90 Angle" airgapwidth=10
RoomDefinition BGA [False] p1: confinementstyle=ConfineIn formatcopy=TRUE lockcomponents=FALSE outline 159.9,560.65 159.9,1135.77 747.82,1135.77 747.82,560.65
RoutingVias [All] p1: holewidth=8 width=16 viastyle="Through Hole" minholewidth=7.87 minwidth=16 maxholewidth=10 maxwidth=20
ShortCircuit ShortCircuit_J3-MH1 [(ObjectKind = 'Pad') And (Name = 'J3-MH1') And (AsMils(HoleDiameter) = 40)] p1: allowed=TRUE
ShortCircuit [All] p2: allowed=FALSE
SilkToSilkClearance [All] p1: silktosilkclearance=3.94
SilkToSolderMaskClearance SilkToSolderMaskClearance_exeption_1 [(IsPad or IsFill or IsRegion) and (InComponent('R35') or InComponent('R97') or InComponent('R31') or InComponent('R32'))] p1: minsilkscreentomaskgap=3.6 clearancetoexposedcopper=TRUE
SilkToSolderMaskClearance SilkToSolderMaskClearance_exeption [(IsPad or IsFill or IsRegion) and InAnyComponent] p2: minsilkscreentomaskgap=3.94 clearancetoexposedcopper=TRUE
SilkToSolderMaskClearance [All] p3: minsilkscreentomaskgap=3.94 clearancetoexposedcopper=FALSE
SolderMaskExpansion [All] p1: expansion=1.97 istentingtop=FALSE
UnRoutedNet [All] p1: checkbadconnections=TRUE
Width [All] p1: maxlimit=20 minlimit=4 preferedwidth=10 toplayer_minwidth=5.66 toplayer_prefwidth=5.66 midlayer1_minwidth=6.66 midlayer1_maxwidth=10 midlayer2_minwidth=4.5 midlayer2_maxwidth=15 midlayer2_prefwidth=4.5 midlayer3_minwidth=6.66 midlayer3_maxwidth=10 midlayer4_minwidth=6.66 midlayer4_maxwidth=10 midlayer5_minwidth=4.5 midlayer5_maxwidth=15 midlayer5_prefwidth=4.5 midlayer6_minwidth=6.66 midlayer6_maxwidth=10 midlayer7_maxwidth=15 midlayer7_prefwidth=4 midlayer8_prefwidth=4 bottomlayer_minwidth=5 bottomlayer_prefwidth=5.66 minimp=50.000000 maximp=50.000000 favimp=50.000000
21 further rules are at their usual default settings.

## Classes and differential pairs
net class ADC: MCU_ADCIN_A0A1_N MCU_ADCIN_A0A1_P MCU_ADCIN_A2A3_N MCU_ADCIN_A2A3_P MCU_ADCIN_A4A5_N MCU_ADCIN_A4A5_P MCU_ADCIN_A6A7_N MCU_ADCIN_A6A7_P MCU_ADCIN_A8A9_N MCU_ADCIN_A8A9_P MCU_ADCIN_A10A11_N MCU_ADCIN_A10A11_P MCU_ADCIN_A12A13_N MCU_ADCIN_A12A13_P MCU_ADCIN_A14A15_N MCU_ADCIN_A14A15_P MCU_ADCIN_B0B1_N MCU_ADCIN_B0B1_P MCU_ADCIN_B2B3_N MCU_ADCIN_B2B3_P MCU_ADCIN_B4B5_N MCU_ADCIN_B4B5_P MCU_ADCIN_B6B7_N MCU_ADCIN_B6B7_P MCU_ADCIN_B12B13_N MCU_ADCIN_B12B13_P MCU_ADCIN_B16B17_N MCU_ADCIN_B16B17_P MCU_ADCIN_C0 MCU_ADCIN_C1 MCU_ADCIN_C2 MCU_ADCIN_C3 MCU_ADCIN_C4 MCU_ADCIN_C5 MCU_ADCIN_C11 MCU_ADCIN_C12 MCU_ADCIN_C13 MCU_ADCIN_C16 MCU_ADCIN_C17 MCU_ADCIN_D0 MCU_ADCIN_D1 MCU_ADCIN_D2 MCU_ADCIN_D3 MCU_ADCIN_D10 MCU_ADCIN_D11 MCU_ADCIN_D12 MCU_ADCIN_D13 MCU_ADCIN_D16 MCU_ADCIN_D17 MCU_ADCIN_E0 MCU_ADCIN_E1 MCU_ADCIN_E2 MCU_ADCIN_E3 MCU_ADCIN_E10 MCU_ADCIN_E12
net class SD_1: MCU_GPIO248 MCU_GPIO249
net class SD_2: MCU_AIO209 MCU_GPIO48
net class SD_3: MCU_AIO206 MCU_AIO207
net class SD2: MCU_AIO211 MCU_AIO212 MCU_AIO213
net class SD1: MCU_AIO186 MCU_GPIO238 MCU_GPIO242 MCU_GPIO246
net class PWM: MCU_GPIO0 MCU_GPIO1 MCU_GPIO2 MCU_GPIO3 MCU_GPIO4 MCU_GPIO5 MCU_GPIO12 MCU_GPIO13 MCU_GPIO17 MCU_GPIO20 MCU_GPIO21 MCU_GPIO26 MCU_GPIO27 MCU_GPIO28 MCU_GPIO88 MCU_GPIO100
differential pair class 100OHM: MCU_ADCIN_A0A1 MCU_ADCIN_A2A3 MCU_ADCIN_A4A5 MCU_ADCIN_A6A7 MCU_ADCIN_A8A9 MCU_ADCIN_A10A11 MCU_ADCIN_A12A13 MCU_ADCIN_A14A15 MCU_ADCIN_B0B1 MCU_ADCIN_B2B3 MCU_ADCIN_B4B5 MCU_ADCIN_B6B7 MCU_ADCIN_B12B13 MCU_ADCIN_B16B17
component class MCU144E1_SOM_Power: C28 C29 C30 C31 C32 C33 C34 C35 C36 C37 C38 C39 C40 C41 C42 C43 C44 C45 C46 C47 C48 C49 C50 C51 C52 C53 C54 C55 C56 C57 C58 C59 C60 C61 C62 C63 C64 C65 C66 C67 C68 C69 C70 C71 C72 C73 C89 C90 L4 L5 L6 L7 LED1 LED2 R5 R6 R7 R8 R9 R10 R11 R12 R13 R14 R15 R16 R17 R18 R19 R20 R21 R22 R28 R66 R67 R68 R71 R72 R73 R75 R76 R77 R78 TP4 TP5 TP6 TP7 TP8 TP9 TP10 TP11 TP12 TP16 TP17 U2 U3 U7
component class MCU144E1_GPIO_Power: a C1 C2 C3 C4 C5 C6 C7 C8 C9 C10 C11 C12 C13 C14 C15 C16 C17 C18 C19 C20 C21 C22 C23 C24 C25 C26 C27 C76 C81 C88 C91 C92 C93 L1 L2 L3 R3 R4 R23 R24 R25 R26 R27 R29 R45 R52 R54 R55 R81 R82 R83 R84 R86 R88 R89 R90 R91 R92 R93 R94 R95 R96 TP1 TP2 TP3 TP14
component class MCU144E1_EVM_Hardware: !PCB1 FID1 FID2 FID3 FID4 FID5 FID6 Logo1 Logo2 Logo3 Logo4 MH1 MH2 MH3 MH4 ZZ1 ZZ2 ZZ3 ZZ4
component class MCU144E1_Emulation_Connectors: J4 J5 R59 R60 R61 R62 R63 R64 R65 R85 R87
component class MCU144E1_Clock_Reset_Boot: C74 C75 C77 C97 LED3 LED4 R30 R31 R32 R33 R34 R35 R36 R37 R38 R39 R40 R41 R42 R43 R44 R46 R47 R48 R49 R50 R69 R80 R97 S1 SW1 TP13 TP15 U5 U6 Y1
component class MCU144E1_Baseboard_Connectors: J1 J2 J3 R1 R2 R74 R79
component class MCU144E1_ADC: C78 C79 C80 C82 C83 C84 C85 C86 C87 C94 C95 C96 R53 R56 R57 R58 R70 S3 S4 U1 U4 U8
component class Logo: Logo2
component class FiducialMark: FID1 FID2 FID3 FID4 FID5 FID6
component class AssemblyNote: ZZ1 ZZ2 ZZ3 ZZ4
pad class pad1: MH1-1
differential pair MCU_ADCIN_B16B17: +MCU_ADCIN_B16B17_P -MCU_ADCIN_B16B17_N
differential pair MCU_ADCIN_B12B13: +MCU_ADCIN_B12B13_P -MCU_ADCIN_B12B13_N
differential pair MCU_ADCIN_B6B7: +MCU_ADCIN_B6B7_P -MCU_ADCIN_B6B7_N
differential pair MCU_ADCIN_B4B5: +MCU_ADCIN_B4B5_P -MCU_ADCIN_B4B5_N
differential pair MCU_ADCIN_B2B3: +MCU_ADCIN_B2B3_P -MCU_ADCIN_B2B3_N
differential pair MCU_ADCIN_B0B1: +MCU_ADCIN_B0B1_P -MCU_ADCIN_B0B1_N
differential pair MCU_ADCIN_A14A15: +MCU_ADCIN_A14A15_P -MCU_ADCIN_A14A15_N
differential pair MCU_ADCIN_A12A13: +MCU_ADCIN_A12A13_P -MCU_ADCIN_A12A13_N
differential pair MCU_ADCIN_A10A11: +MCU_ADCIN_A10A11_P -MCU_ADCIN_A10A11_N
differential pair MCU_ADCIN_A8A9: +MCU_ADCIN_A8A9_P -MCU_ADCIN_A8A9_N
differential pair MCU_ADCIN_A6A7: +MCU_ADCIN_A6A7_P -MCU_ADCIN_A6A7_N
differential pair MCU_ADCIN_A4A5: +MCU_ADCIN_A4A5_P -MCU_ADCIN_A4A5_N
differential pair MCU_ADCIN_A2A3: +MCU_ADCIN_A2A3_P -MCU_ADCIN_A2A3_N
differential pair MCU_ADCIN_A0A1: +MCU_ADCIN_A0A1_P -MCU_ADCIN_A0A1_N

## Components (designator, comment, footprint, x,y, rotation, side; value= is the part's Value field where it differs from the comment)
C1 "GRM155R61A106ME18D" FP-GRM155R61A106ME18D_0402-MFG 436.76,1431.92 r270 top value=10µF
C2 "GRM155R61A106ME18D" FP-GRM155R61A106ME18D_0402-MFG 437.26,1254.3 r0 top value=10µF
C3 "GRM155R61E225ME15D" 0402 333,525.87 r270 top value=2.2uF
C4 "GRM155R61E225ME15D" 0402 828.63,645.05 r180 top value=2.2uF
C5 "GRM155R61E225ME15D" 0402 828.16,505.98 r180 bottom value=2.2uF
C6 "GRM155R71E104KE14D" 0402 438.64,1208.8 r180 top value=0.1uF
C7 "GRM155R71E104KE14D" 0402 436.64,1235.8 r180 bottom value=0.1uF
C8 "GRM155R71E104KE14D" 0402 436.64,1194.8 r180 bottom value=0.1uF
C9 "GRM155R71E104KE14D" 0402 438.64,1167.8 r180 top value=0.1uF
C10 "GRM155R71E104KE14D" 0402 391.76,848.21 r0 bottom value=0.1uF
C11 "GRM155R71E104KE14D" 0402 528.76,848.21 r180 bottom value=0.1uF
C12 "GRM155R71E104KE14D" 0402 461.95,962.47 r270 bottom value=0.1uF
C13 "GRM155R61E225ME15D" 0402 295.13,848.21 r180 bottom value=2.2uF
C14 "GRM155R61E225ME15D" 0402 318,529.79 r270 bottom value=2.2uF
C15 "GRM155R71E104KE14D" 0402 436.64,1153.8 r180 bottom value=0.1uF
C16 "GRM155R71E104KE14D" 0402 828.63,872.3 r0 top value=0.1uF
C17 "GRM155R71E104KE14D" 0402 828.63,831.3 r0 bottom value=0.1uF
C18 "GRM155R71E104KE14D" 0402 828.63,831.3 r0 top value=0.1uF
C19 "GRM155R71E104KE14D" 0402 95.1,846.91 r270 top value=0.1uF
C20 "GRM155R71E104KE14D" 0402 572.16,496.23 r270 bottom value=0.1uF
C21 "GRM155R71E104KE14D" 0402 144.93,846.91 r270 top value=0.1uF
C22 "GRM155R71E104KE14D" 0402 490.16,496.23 r270 bottom value=0.1uF
C23 "GRM155R71E104KE14D" 0402 531.16,496.23 r270 bottom value=0.1uF
C24 "GRM155R71E104KE14D" 0402 531.16,496.23 r270 top value=0.1uF
C25 "GRM155R71E104KE14D" 0402 572.16,496.23 r270 top value=0.1uF
C26 "GRM155R71E104KE14D" 0402 828.63,872.3 r0 bottom value=0.1uF
C27 "GRM155R71E104KE14D" 0402 613.16,496.25 r270 bottom value=0.1uF
C28 "GRM21BR61E226ME44L" 0805_HV 1410,855 r0 bottom value=22uF
C29 "GRM21BR61E226ME44L" 0805_HV 1250,845 r180 top value=22uF
C30 "GRM21BR61E226ME44L" 0805_HV 1243,927 r180 bottom value=22uF
C31 "GRM155R61E225ME15D" 0402 1390,975 r0 bottom value=2.2uF
C32 "GRM155R61E225ME15D" 0402 1250,915 r180 top value=2.2uF
C33 "GRM1555C1H102JA01D" 0402 1390,975 r0 top value=1000pF
C34 "GRM1555C1H102JA01D" 0402 1264.08,959.68 r180 top value=1000pF
C35 "GRM155R71E104KE14D" 0402 1390,925 r0 bottom value=0.1uF
C36 "GRM155R71E104KE14D" 0402 1390,925 r0 top value=0.1uF
C37 "GRM155R71E104KE14D" 0402 1413.3,1026.32 r0 top value=0.1uF
C38 "GRM155R71E104KE14D" 0402 1265.32,1519 r0 top value=0.1uF
C39 "GRM155R71E104KE14D" 0402 1267.46,1032.64 r0 top value=0.1uF
C40 "GRM155R71E104KE14D" 0402 1338.22,650 r0 top value=0.1uF
C41 "GRM155R61E225ME15D" 0402 1404,1397.38 r90 bottom value=2.2uF
C42 "GRM155C61E475ME15D" FP-GRM155C61E475ME15D_0402-MFG 1358.5,1398.76 r270 bottom value=4.7µF
C43 "GRM21BR61A476ME15L" 0805_HV 1521.92,384.37 r0 bottom value=47uF
C44 "GRM21BR61A476ME15L" 0805_HV 1521.38,384.37 r0 top value=47uF
C45 "GRM155R71E104KE14D" 0402 1242.64,701.53 r180 top value=0.1uF
C46 "GRM155R61A106ME18D" FP-GRM155R61A106ME18D_0402-MFG 1547.92,696.52 r180 top value=10µF
C47 "GJM1555C1H470JB01D" FP-GJM1555C1H470JB01D_0402-MFG 1555.8,800.36 r180 top value=47pF
C48 "GRM21BR61E226ME44L" 0805_HV 1410,855 r0 top value=22uF
C49 "GRM155R61A106ME18D" FP-GRM155R61A106ME18D_0402-MFG 1642,1001 r180 bottom value=10µF
C50 "GRM21BR61A476ME15L" 0805_HV 1521.38,474.37 r0 top value=47uF
C51 "GRM1555C1H102JA01D" 0402 1547.87,847.93 r180 bottom value=1000pF
C52 "GRM155R61A106ME18D" FP-GRM155R61A106ME18D_0402-MFG 1514.76,947.81 r180 bottom value=10µF
C53 "GRM155R61A106ME18D" FP-GRM155R61A106ME18D_0402-MFG 1306.67,355.4 r0 bottom value=10µF
C54 "GRM21BR61E226ME44L" 0805_HV 1181.93,1681.12 r90 top value=22uF
C55 "GRM21BR61E226ME44L" 0805_HV 1094.14,1681.12 r90 top value=22uF
C56 "GRM21BR61E226ME44L" 0805_HV 1269.03,1681.12 r90 top value=22uF
C57 "GRM1555C1H102JA01D" 0402 1375.99,1551.34 r0 top value=1000pF
C58 "GRM155R71E104KE14D" 0402 1375.99,1599.77 r0 top value=0.1uF
C59 "GRM155R71E104KE14D" 0402 1375.99,1648.35 r0 top value=0.1uF
C60 "GRM155R71E104KE14D" 0402 1375.99,1551.34 r0 bottom value=0.1uF
C61 "GRM155R61A106ME18D" FP-GRM155R61A106ME18D_0402-MFG 1715,1560 r270 bottom value=10µF
C62 "GRM155R71E104KE14D" 0402 1517.38,1541.81 r0 top value=0.1uF
C63 "GRM155R61A106ME18D" FP-GRM155R61A106ME18D_0402-MFG 1517.38,1589 r180 top value=10µF
C64 "GRM155R71E104KE14D" 0402 1516.13,997 r0 top value=0.1uF
C65 "GRM155R61A106ME18D" FP-GRM155R61A106ME18D_0402-MFG 1516.13,997 r180 bottom value=10µF
C66 "GRM188R61C106MAALD" 0603 840,1435 r270 top value=10uF
C67 "GRM155R71E104KE14D" 0402 1642,1001 r0 top value=0.1uF
C68 "GRM21BR61E226ME44L" 0805_HV 759,1330 r0 top value=22uF
C69 "GRM155R71E104KE14D" 0402 1610,1573.62 r90 top value=0.1uF
C70 "GRM155R61A106ME18D" FP-GRM155R61A106ME18D_0402-MFG 1637.17,1559.71 r180 bottom value=10µF
C71 "GRM155R71E104KE14D" 0402 1715,957.87 r270 top value=0.1uF
C72 "GRM155R61A106ME18D" FP-GRM155R61A106ME18D_0402-MFG 1715,958 r90 bottom value=10µF
C73 "GRM155R71E104KE14D" 0402 1665,1573.62 r90 top value=0.1uF
C74 "GRM155R71E104KE14D" 0402 1001.78,360.19 r0 top value=0.1uF
C75 "GRM155R71E104KE14D" 0402 1100.37,822.19 r90 top value=0.1uF
C76 "GRM155R71E104KE14D" 0402 613.16,496.25 r270 top value=0.1uF
C77 "GRM155R71E104KE14D" 0402 575,1821 r180 top value=0.1uF
C78 "GRM155R61E105KE11D" 0402 46.95,311.35 r0 top value=1uF
C79 "GRM155R61E105KE11D" 0402 109.75,589.22 r90 top value=1uF
C80 "GRM155C61E475ME15D" FP-GRM155C61E475ME15D_0402-MFG 156.09,441.14 r90 top value=4.7µF
C81 "GRM155R71E104KE14D" 0402 460.26,697.09 r270 bottom value=0.1uF
C82 "GRM155C61E475ME15D" FP-GRM155C61E475ME15D_0402-MFG 50,610 r90 top value=4.7µF
C83 "GRM155R71E104KE14D" 0402 -346.41,663.64 r90 top value=0.1uF
C84 "GRM155R61E225ME15D" 0402 150,155 r0 top value=2.2uF
C85 "GRM155R71E104KE14D" 0402 124.28,238.09 r90 top value=0.1uF
C86 "GRM155R61A106ME18D" FP-GRM155R61A106ME18D_0402-MFG -204.32,231.61 r0 top value=10µF
C87 "GRM155R61E105KE11D" 0402 -206,310 r90 top value=1uF
C88 "GRM155R71E104KE14D" 0402 624.76,848.21 r0 bottom value=0.1uF
C89 "GRM21BR61E226ME44L" 0805_HV 1250.18,845.16 r180 bottom value=22uF
C90 "GRM21BR61E226ME44L" 0805_HV 1250.51,761.64 r180 bottom value=22uF
C91 "GRM155R71E104KE14D" 0402 460.26,793.09 r90 bottom value=0.1uF
C92 "GRM155R61E225ME15D" 0402 490.16,497.23 r90 top value=2.2uF
C93 "GRM155R71E104KE14D" 0402 144.93,846.91 r90 bottom value=0.1uF
C94 "GRM155R61E105KE11D" 0402 -239.39,685.24 r270 top value=1uF
C95 "GRM155R61E105KE11D" 0402 -241.73,885.45 r90 top value=1uF
C96 "885012006060" 0603 365.77,517.81 r270 bottom value=330pF
C97 "GRM1555C1H201JA01D" 0402 639.86,1087.04 r0 bottom value=200pF
FID1 "Fiducial" FIDUCIAL10-20 2225.25,2016.96 r90 top
FID2 "Fiducial" FIDUCIAL10-20 2225.25,2016.96 r90 bottom
FID3 "Fiducial" FIDUCIAL10-20 2225.25,-50 r90 top
FID4 "Fiducial" FIDUCIAL10-20 2225.25,-50 r90 bottom
FID5 "Fiducial" FIDUCIAL10-20 -320,-50 r90 top
FID6 "Fiducial" FIDUCIAL10-20 -320,-50 r90 bottom
J1 "QSH-060-01-L-D-A" CONN_QSH-060-01-L-D-A 985,140 r180 bottom locked
J2 "QSH-060-01-L-D-A" CONN_QSH-060-01-L-D-A -100,955 r270 bottom locked
J3 "QSH-060-01-L-D-A" CONN_QSH-060-01-L-D-A 2065,955 r90 bottom locked
J4 "TSM-108-01-L-DV-008-P-TR" FP-TSM-108-01-L-DV-008-P-TR_HDR15-MFG 1313,110 r180 top locked
J5 "QSH-030-01-L-D-A" FP-QSH-030-01-L-D-A_CONN_60-MFG 2065,561.3 r270 top locked
L1 "BLM21PG221SN1D" 0805_HV 559.49,1292.02 r270 top value="220 ohm"
L2 "60ohm" 0603 828.16,553.68 r180 bottom value="60 ohm"
L3 "60ohm" 0603 828.16,582.23 r180 top value="60 ohm"
L4 "SPM7054VT-2R2M-D" FP-SPM7054VT-2R2M-D_SMT_IND_7MM5_7MM0-MFG 1042,1285.74 r90 top value=2.2uH
L5 "DFE252012P-1R5M=P2" DFE252012P 1427.56,570 r180 top value=1.5uH
L6 "60ohm" 0603 1526.57,949.23 r0 top value="60 ohm"
L7 "XGL4030-102MEC" FP-XGL4030-102MEC_SMD_IND_4MM0_4MM0-MFG 560.44,1453.86 r270 top value=1uH
LED1 "APHHS1005SURCK" APHHS1005_RED 1938.84,9.16 r90 top value=Red
LED2 "APHHS1005SURCK" APHHS1005_RED 2154.84,16.28 r90 top value=Red
LED3 "APHHS1005CGCK" APHHS1005_GREEN 2171.84,1055.99 r0 top value=Green
LED4 "APHHS1005CGCK" APHHS1005_GREEN 2175.97,1169.19 r0 top value=Green
Logo1 "CE Mark" CE_MARK_5MM 1068,1428 r180 bottom
Logo2 "Texas Instruments" TI_STACKED_OVERLAY_SMALL 1366.87,2001.47 r0 top
Logo3 "FCC disclaimer" FCC_DISCLAIMER 1873.77,1451.38 r90 top
Logo4 "WEEE logo" WEEE_Minimum 240,1580 r180 bottom
MH1 "MTG_NoPads" MTG_159mil 0,0 r0 top locked
MH2 "MTG_NoPads" MTG_159mil 1760,435 r0 top locked
MH3 "MTG_NoPads" MTG_159mil 1970,1905 r0 top locked
MH4 "MTG_NoPads" MTG_159mil 0,1905 r0 top locked
R1 "CRG0402F4K7" 0402 1389,346 r0 top value=4.70k
R2 "AC0402FR-0710KL" 0402 1293,346 r0 top value=10.0k
R3 "AC0402FR-0710KL" 0402 1790.75,620.07 r90 top value=10.0k
R4 "CRG0402F4K7" 0402 1517.38,1541.81 r180 bottom value=4.70k
R5 "RC0402FR-0712KL" "FP-RC0402FR-0712KL_0402 (1005 METRIC)-MFG" 1215,1145 r180 bottom value=12k
R6 "AC0402FR-0710KL" 0402 1309.57,1022.65 r0 bottom value=10.0k
R7 "CRCW04020000Z0ED" 0402 1188,1044 r90 top value=0
R8 "RC0402FR-073KL" 0402 1377.92,1127.12 r270 bottom value=3.00k
R9 "CRCW04023K90JNED" 0402 1171.61,941.49 r90 top value=3.9k
R10 "CRG0402F4K7" 0402 1794.36,1539.37 r0 bottom value=4.70k
R11 "AC0402FR-0710KL" 0402 1769.3,1545 r180 top value=10.0k
R12 "CRCW0402301KFKED" 0402 1434.22,650 r180 top value=301k
R13 "CRCW040223K7FKED" 0402 1547.87,798.19 r180 bottom value=23.7k
R14 "CRCW04021M05FKED" 0402 1547.92,748.33 r0 top value=1.05Meg
R15 "CRCW04020000Z0ED" 0402 1640,1440 r0 bottom value=0
R16 "CRG0402F4K7" 0402 1777.07,1403.68 r0 top value=4.70k
R17 "CRCW0402174KFKED" 0402 1242.64,751.53 r0 top value=174k
R18 "CRCW0402118KFKED" 0402 1547.87,746.42 r180 bottom value=118k
R19 "RC0402FR-073KL" 0402 1881.81,19.13 r90 top value=3.00k
R20 "CRCW04021K20JNED" 0402 2099.84,21.28 r90 top value=1.2k
R21 "AC0402FR-0710KL" 0402 830,1425 r90 bottom value=10.0k
R22 "CRCW04020000Z0ED" 0402 871,1425 r270 bottom value=0
R23 "AC0402FR-0710KL" 0402 1750.74,620.07 r90 top value=10.0k
R24 "AC0402FR-0710KL" 0402 1710.74,620.07 r90 top value=10.0k
R25 "CRCW04020000Z0ED" 0402 877.92,979.94 r180 top value=0
R26 "CRCW04020000Z0ED" 0402 854.3,956.32 r90 top value=0
R27 "CRCW04020000Z0ED" 0402 830.67,932.7 r180 top value=0
R28 "CRCW04020000Z0ED" 0402 765,1580 r270 top value=0
R29 "CRCW04020000Z0ED" 0402 875.53,1087.58 r180 top value=0
R30 "AC0402FR-0710KL" 0402 1112.64,580.38 r0 top value=10.0k
R31 "CRCW04020000Z0ED" 0402 1202.16,452.5 r0 top value=0
R32 "CRCW04020000Z0ED" 0402 1154.92,452.5 r180 top value=0
R33 "AC0402FR-0710KL" 0402 1112.64,530.38 r180 top value=10.0k
R34 "CRCW040275R0FKED" 0402 976.97,731.42 r90 top value=75.0
R35 "CRCW04020000Z0ED" 0402 722.66,423.69 r180 top value=0
R36 "CRCW04020000Z0ED" 0402 1054.77,727.19 r0 top value=0
R37 "CRCW04020000Z0ED" 0402 1034.77,916.39 r0 top value=0
R38 "CRCW040275R0FKED" 0402 1112.64,399.02 r0 top value=75.0
R39 "AC0402FR-0710KL" 0402 654.16,486.26 r270 top value=10.0k
R40 "AC0402FR-0710KL" 0402 695.16,496.26 r270 top value=10.0k
R41 "CRCW04022K20FKED" 0402 736.16,496.26 r270 top value=2.20k
R42 "CRCW04022K49FKED" 0402 2275,1453.62 r270 top value=2.49k
R43 "CRCW04022K49FKED" 0402 1923.36,1599.64 r0 top value=2.49k
R44 "AC0402FR-0710KL" 0402 870.64,205.85 r90 top value=10.0k
R45 "CRCW04020000Z0ED" 0402 851.9,1063.96 r90 top value=0
R46 "CRCW04023K30JNED" 0402 574.63,1161.71 r90 bottom value=3.3k
R47 "CRCW04021K20JNED" 0402 2178.84,1106.99 r0 top value=1.2k
R48 "CRCW04021K20JNED" 0402 2181.24,1220.57 r0 top value=1.2k
R49 "CRG0402F4K7" 0402 575,1921 r180 top value=4.70k
R50 "CRG0402F4K7" 0402 575,1971 r180 top value=4.70k
R52 "CRCW04020000Z0ED" 0402 828.63,697.3 r180 top value=0
R53 "ERJ-2RKF1001X" 0402 -54.91,311.26 r180 top value=1.00k
R54 "CRCW04020000Z0ED" 0402 828.28,1040.34 r180 top value=0
R55 "CRCW04020000Z0ED" 0402 214.63,1184.82 r270 bottom value=0
R56 "ERJ2BWFR100X" 0402 109.99,483.98 r90 top value=0.1
R57 "ERJ-2RKF1001X" 0402 -239.39,781.24 r90 top value=1.00k
R58 "ERJ2BWFR100X" 0402 52,694 r90 top value=0.1
R59 "CRCW0402100RFKED" 0402 1880.05,905.42 r270 top value=100
R60 "CRCW04020000Z0ED" 0402 1788.03,172.01 r0 top value=0
R61 "CRCW04020000Z0ED" 0402 1788.03,111.85 r0 top value=0
R62 "CRCW04020000Z0ED" 0402 1788.03,-8.46 r0 top value=0
R63 "CRCW04020000Z0ED" 0402 1788.03,51.69 r0 top value=0
R64 "CRCW04020000Z0ED" 0402 2272.29,830.05 r270 top value=0
R65 "CRCW04020000Z0ED" 0402 1849.55,800.19 r270 top value=0
R66 "CRCW04020000Z0ED" 0402 1300.83,1105 r180 bottom value=0
R67 "CRCW04020000Z0ED" 0402 1400,732 r0 bottom value=0
R68 "CRCW04020000Z0ED" 0402 1400,775 r180 bottom value=0
R69 "CRCW04020000Z0ED" 0402 575,1871 r180 top value=0
R70 "ERJ-3GEY0R00V" 0603 420.17,517.81 r90 bottom value=0
R71 "CRCW04020000Z0ED" 0402 1492.3,1436.77 r180 bottom value=0
R72 "CRCW040216K2FKED" 0402 750.13,1260.41 r180 top value=16.2k
R73 "CRCW0402162KFKED" 0402 711.5,1419.11 r270 bottom value=162k
R74 "CRCW04020000Z0ED" 0402 1369.72,370.94 r90 bottom value=0
R75 "AC0402FR-0710KL" 0402 683,1580 r90 top value=10.0k
R76 "CRCW0402150KFKED" 0402 753.23,1419.11 r90 bottom value=150k
R77 "CRCW040215K0FKED" 0402 750.13,1260.41 r0 bottom value=15.0k
R78 "CRCW040220K0FKED" 0402 724,1580 r270 top value=20.0k
R79 "CRCW04020000Z0ED" 0402 779.3,248.32 r90 top value=0
R80 "CRCW040275R0FKED" 0402 865.9,423.69 r180 top value=75.0
R81 "CRCW04020000Z0ED" 0402 117.38,986.62 r0 top value=0
R82 "CRCW04020000Z0ED" 0402 828.63,697.3 r180 bottom value=0
R83 "CRCW04020000Z0ED" 0402 255.63,1184.82 r270 bottom value=0
R84 "CRCW04020000Z0ED" 0402 117.38,946.24 r0 top value=0
R85 "CRCW0402100RFKED" 0402 2272.72,725.84 r90 top value=100
R86 "CRCW04020000Z0ED" 0402 828.63,779.3 r180 top value=0
R87 "CRCW04020000Z0ED" 0402 1849.55,684.19 r90 top value=0
R88 "CRCW04020000Z0ED" 0402 296.63,1184.82 r270 bottom value=0
R89 "CRCW04020000Z0ED" 0402 628.5,1186.41 r270 bottom value=0
R90 "CRCW04020000Z0ED" 0402 828.63,779.3 r180 bottom value=0
R91 "CRCW04020000Z0ED" 0402 337.63,1184.82 r270 bottom value=0
R92 "CRCW04020000Z0ED" 0402 700.54,1163.36 r270 bottom value=0
R93 "CRCW04020000Z0ED" 0402 828.63,738.3 r180 top value=0
R94 "CRCW04020000Z0ED" 0402 118.64,1170.51 r0 top value=0
R95 "CRCW04020000Z0ED" 0402 828.63,738.3 r180 bottom value=0
R96 "CRCW04020000Z0ED" 0402 117.46,1111.89 r0 top value=0
R97 "CRCW04020000Z0ED" 0402 769.9,423.69 r0 top value=0
S1 "CAS-D20TA" SW_CAS-D20TA 2071.17,1451.1 r180 top
S3 "CAS-D20TA" SW_CAS-D20TA -56,468 r180 top
S4 "CAS-D20TA" SW_CAS-D20TA -94.17,706.9 r180 top
SW1 "PTS810 SJG 250 SMTR LFS" "FP-PTS810 SJG 250 SMTR LFS_SW_SMT_4MM2_3MM2-MFG" 259.49,1732.64 r90 top
TP1 "CMP-0078143-4" TESTPOINT 413.92,1332.92 r90 top
TP2 "CMP-0078143-4" TESTPOINT 166.55,1330.18 r180 top
TP3 "CMP-0078143-4" TESTPOINT 1780,1265 r90 top
TP4 "TP_SM_1MM" TP_SM_1MM 1746,1471 r90 top
TP5 "CMP-0078143-4" TESTPOINT 1304.31,526.98 r90 top
TP6 "TP_SM_1MM" TP_SM_1MM 1814.24,935.79 r90 top
TP7 "TP_SM_1MM" TP_SM_1MM 1790,1000 r90 top
TP8 "CMP-0078143-4" TESTPOINT 1730,721.8 r90 top
TP9 "TP_SM_1MM" TP_SM_1MM 1715,1601 r0 top
TP10 "TP_SM_1MM" TP_SM_1MM 1850,999.56 r90 top
TP11 "TP_SM_1MM" TP_SM_1MM 840,1540 r90 top
TP12 "TP_SM_1MM" TP_SM_1MM 1637,930.95 r0 top
TP13 "TP_SM_1MM" TP_SM_1MM 909.23,349.63 r90 top
TP14 "CMP-0078143-4" TESTPOINT -327.51,117.95 r270 top
TP15 "CMP-0078143-4" TESTPOINT 415.49,1873.61 r180 top
TP16 "CMP-0078143-4" TESTPOINT 1501.78,1697.21 r0 bottom
TP17 "CMP-0078143-4" TESTPOINT 1730,847 r90 top
U1 "F29H850TU9TZEXR" ZEX0256A-MFG 460.26,848.21 r0 top locked
U2 "TPS6538600QDCARQ1" DCA0048J-MFG 1457.94,1285.74 r90 top
U3 "TPS61089RNRR" RNR0011A 1386.22,730.87 r180 top
U4 "OPA2320AIDGKT" DGK0008A_N -307.61,468 r90 top
U5 "LMK1C1103PWR" PW0008A-MFG 989.77,532.19 r270 top
U6 "CAT24C16WI-GT3" SOIC-8 768,1897 r180 top
U7 "TPS62902QRYTRQ1" RYT0009A-MFG 728.21,1463.11 r0 top
U8 "REF5030IDGKT" DGK0008A_N -24.21,226.82 r180 top
Y1 "LMK6CE02500CDLFT" DLF0004A-MFG 1027,834.2 r270 top
ZZ1 "This Assembly Note is for PCB labels only" ASSEMBLYNOTELABEL -580,2555 r0 top
ZZ2 "These assemblies are ESD sensitive, ESD precautions shall be observed." ASSEMBLYNOTE -580,2655 r0 top
ZZ3 "These assemblies must be clean and free from flux and all contaminants. Use of no clean flux is not acceptable." ASSEMBLYNOTE -580,2750 r0 top
ZZ4 "These assemblies must comply with workmanship standards IPC-A-610 Class 2, unless otherwise specified." ASSEMBLYNOTE -580,2850 r0 top

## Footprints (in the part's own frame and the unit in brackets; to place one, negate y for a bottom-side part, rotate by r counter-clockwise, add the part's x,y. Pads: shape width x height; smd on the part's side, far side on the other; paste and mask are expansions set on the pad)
0402 [mm] "0402 from SM-752 data"
  rect 0.8x0.6 smd: 1(-0.6,0) 2(0.6,0)
  silkscreen extent -1.22,-0.52 1.22,0.52, body extent -0.55,-0.3 0.55,0.3, height 0.6
0603 [mm] "0603 from SM-752 data"
  rect 1x0.95 smd: 1(-0.8,0) 2(0.8,0)
  silkscreen extent -1.52,-0.69 1.52,0.69, body extent -0.87,-0.47 0.87,0.47, height 1
0805_HV [mil] "0805 with 30mil clearance between pads"
  rect 50x63 smd: 1(-40,0) 2(40,0)
  silkscreen extent -74,-40 74,40, body extent -43,-29 43,29, height 57
APHHS1005_GREEN [mm] "SMD, 2-Leads, Body 1x0.5mm"
  rrect20% 0.7x0.5 smd: 1(-0.45,0) 2(0.45,0)
  silkscreen extent -0.8,-0.65 1.2,0.65, body extent -0.5,-0.25 0.5,0.25, height 0.5
APHHS1005_RED [mm] "SMD, 2-Leads, Body 1x0.5mm"
  rrect20% 0.7x0.5 smd: 1(-0.45,0) 2(0.45,0)
  silkscreen extent -0.8,-0.65 1.2,0.65, body extent -0.5,-0.25 0.5,0.25, height 0.5
ASSEMBLYNOTE [mil] "Assembly Note"
ASSEMBLYNOTELABEL [mil] "Assembly Note for PCB Labels"
CE_MARK_5MM [mil] "Minimum text height for CE Mark"
  silkscreen extent -138,-99 138,99
CONN_QSH-060-01-L-D-A [mil] "SAMTEC"
  rect 11x90 smd: 1(-679.23,-112.41) 2(-679.23,113.19) 3(-659.55,-112.41) 4(-659.55,113.19) 5(-639.86,-112.41) 6(-639.86,113.19) 7(-620.18,-112.41) 8(-620.18,113.19) 9(-600.49,-112.41) 10(-600.49,113.19) 11(-580.81,-112.41) 12(-580.81,113.19) 13(-561.12,-112.41) 14(-561.12,113.19) 15(-541.44,-112.41) 16(-541.44,113.19) 17(-521.75,-112.41) 18(-521.75,113.19) 19(-502.07,-112.41) 20(-502.07,113.19) 21(-482.38,-112.41) 22(-482.38,113.19) 23(-462.7,-112.41) 24(-462.7,113.19) 25(-443.01,-112.41) 26(-443.01,113.19) 27(-423.33,-112.41) 28(-423.33,113.19) 29(-403.64,-112.41) 30(-403.64,113.19) 31(-383.96,-112.41) 32(-383.96,113.19) 33(-364.27,-112.41) 34(-364.27,113.19) 35(-344.59,-112.41) 36(-344.59,113.19) 37(-324.9,-112.41) 38(-324.9,113.19) 39(-305.22,-112.41) 40(-305.22,113.19) 41(-285.53,-112.41) 42(-285.53,113.19) 43(-265.85,-112.41) 44(-265.85,113.19) 45(-246.16,-112.41) 46(-246.16,113.19) 47(-226.48,-112.41) 48(-226.48,113.19) 49(-206.79,-112.41) 50(-206.79,113.19) 51(-187.11,-112.41) 52(-187.11,113.19) 53(-167.42,-112.41) 54(-167.42,113.19) 55(-147.74,-112.41) 56(-147.74,113.19) 57(-128.05,-112.41) 58(-128.05,113.19) 59(-108.37,-112.41) 60(-108.37,113.19) 61(108.29,-112.41) 62(108.29,113.19) 63(127.97,-112.41) 64(127.97,113.19) 65(147.66,-112.41) 66(147.66,113.19) 67(167.34,-112.41) 68(167.34,113.19) 69(187.03,-112.41) 70(187.03,113.19) 71(206.71,-112.41) 72(206.71,113.19) 73(226.4,-112.41) 74(226.4,113.19) 75(246.08,-112.41) 76(246.08,113.19) 77(265.77,-112.41) 78(265.77,113.19) 79(285.45,-112.41) 80(285.45,113.19) 81(305.14,-112.41) 82(305.14,113.19) 83(324.82,-112.41) 84(324.82,113.19) 85(344.51,-112.41) 86(344.51,113.19) 87(364.19,-112.41) 88(364.19,113.19) 89(383.88,-112.41) 90(383.88,113.19) 91(403.56,-112.41) 92(403.56,113.19) 93(423.25,-112.41) 94(423.25,113.19) 95(442.93,-112.41) 96(442.93,113.19) 97(462.62,-112.41) 98(462.62,113.19) 99(482.3,-112.41) 100(482.3,113.19) 101(501.99,-112.41) 102(501.99,113.19) 103(521.67,-112.41) 104(521.67,113.19) 105(541.36,-112.41) 106(541.36,113.19) 107(561.04,-112.41) 108(561.04,113.19) 109(580.73,-112.41) 110(580.73,113.19) 111(600.41,-112.41) 112(600.41,113.19) 113(620.1,-112.41) 114(620.1,113.19) 115(639.78,-112.41) 116(639.78,113.19) 117(659.47,-112.41) 118(659.47,113.19) 119(679.15,-112.41) 120(679.15,113.19)
  rect 100x16.93 smd: 121(-711.22,0) 124(-76.18,0) 125(76.18,0) 128(711.22,0)
  rect 185.04x16.93 smd: 122(-518.7,0) 123(-268.7,0) 126(268.7,0) 127(518.7,0)
  round 35 hole 40 unplated: MH1(-789.96,105.12) MH2(789.96,105.12)
  body extent -811,-143 814,142, height 128
DCA0048J-MFG [mm]
  rrect33% 1.5x0.3 smd paste+0 mask+0: 1(-3.75,5.75) 2(-3.75,5.25) 3(-3.75,4.75) 4(-3.75,4.25) 5(-3.75,3.75) 6(-3.75,3.25) 7(-3.75,2.75) 8(-3.75,2.25) 9(-3.75,1.75) 10(-3.75,1.25) 11(-3.75,0.75) 12(-3.75,0.25) 13(-3.75,-0.25) 14(-3.75,-0.75) 15(-3.75,-1.25) 16(-3.75,-1.75) 17(-3.75,-2.25) 18(-3.75,-2.75) 19(-3.75,-3.25) 20(-3.75,-3.75) 21(-3.75,-4.25) 22(-3.75,-4.75) 23(-3.75,-5.25) 24(-3.75,-5.75) 25(3.75,-5.75) 26(3.75,-5.25) 27(3.75,-4.75) 28(3.75,-4.25) 29(3.75,-3.75) 30(3.75,-3.25) 31(3.75,-2.75) 32(3.75,-2.25) 33(3.75,-1.75) 34(3.75,-1.25) 35(3.75,-0.75) 36(3.75,-0.25) 37(3.75,0.25) 38(3.75,0.75) 39(3.75,1.25) 40(3.75,1.75) 41(3.75,2.25) 42(3.75,2.75) 43(3.75,3.25) 44(3.75,3.75) 45(3.75,4.25) 46(3.75,4.75) 47(3.75,5.25) 48(3.75,5.75)
  rrect2% 5.1x12.5 smd paste-1000 mask-1000: 49(0,0)
  silkscreen extent -5.2,-6.3 3.1,6.3, body extent -4.6,-6.55 4.6,6.55, height 0.25
DFE252012P [mm] "TOKO, Pad sizes increased as per request"
  rect 0.9x2 smd: 1(-1.05,0) 2(1.05,0)
  silkscreen extent -0.3,-1.2 0.3,1.2, body extent -1.35,-1.1 1.35,1.1, height 1.2
DGK0008A_N [mm] "TSOP, 8-Leads, Body 3x3mm, Pitch 0.65mm, IPC Medium Density"
  oval 1.35x0.45 smd: 1(-2.225,0.975) 2(-2.225,0.325) 3(-2.225,-0.325) 4(-2.225,-0.975) 5(2.225,-0.975) 6(2.225,-0.325) 7(2.225,0.325) 8(2.225,0.975)
  silkscreen extent -2.75,-1.55 0.95,1.55, body extent -2.45,-1.5 2.45,1.5, height 0.96
DLF0004A-MFG [mm]
  rrect15% 0.9x0.65 smd paste-1000 mask+0: 1(-0.75,0.825) 2(-0.75,-0.825) 3(0.75,-0.825) 4(0.75,0.825)
  silkscreen extent -1.55,-0.13 1.05,0.37, body extent -1,-1.25 1,1.25, height 1
FCC_DISCLAIMER [mil]
FIDUCIAL10-20 [mm]
  round 1 smd mask+0.5: 1(0,0)
  Top Layer keep-out circle w1.178: c0,0 r0.5
FP-GJM1555C1H470JB01D_0402-MFG [mm]
  rrect25% 0.4x0.5 smd paste+0 mask+0: 1(-0.4,0) 2(0.4,0)
  silkscreen extent -0.53,-0.63 0.53,0.63, body extent -0.7,-0.38 0.7,0.38, height 0.25
FP-GRM155C61E475ME15D_0402-MFG [mm]
  rrect22% 0.45x0.6 smd paste+0 mask+0: 1(-0.475,0) 2(0.475,0)
  silkscreen extent -0.6,-0.64 0.6,0.65, body extent -0.5,-0.25 0.5,0.25, height 0.7
FP-GRM155R61A106ME18D_0402-MFG [mm]
  rrect22% 0.45x0.6 smd paste+0 mask+0: 1(-0.475,0) 2(0.475,0)
  silkscreen extent -0.6,-0.64 0.6,0.65, body extent -0.8,-0.45 0.8,0.45, height 0.25
"FP-PTS810 SJG 250 SMTR LFS_SW_SMT_4MM2_3MM2-MFG" [mm]
  rrect15% 1.05x0.65 smd paste+0 mask+0: 1(-2.075,1.075) 2(2.075,1.075) 3(-2.075,-1.075) 4(2.075,-1.075)
  body extent -2.7,-1.7 2.7,1.7, height 0.25
FP-QSH-030-01-L-D-A_CONN_60-MFG [mm]
  rrect36% 0.279x2.27 smd paste+0 mask+0: 1(-7.25,-2.865) 2(-7.25,2.865) 3(-6.75,-2.865) 4(-6.75,2.865) 5(-6.25,-2.865) 6(-6.25,2.865) 7(-5.75,-2.865) 8(-5.75,2.865) 9(-5.25,-2.865) 10(-5.25,2.865) 11(-4.75,-2.865) 12(-4.75,2.865) 13(-4.25,-2.865) 14(-4.25,2.865) 15(-3.75,-2.865) 16(-3.75,2.865) 17(-3.25,-2.865) 18(-3.25,2.865) 19(-2.75,-2.865) 20(-2.75,2.865) 21(-2.25,-2.865) 22(-2.25,2.865) 23(-1.75,-2.865) 24(-1.75,2.865) 25(-1.25,-2.865) 26(-1.25,2.865) 27(-0.75,-2.865) 28(-0.75,2.865) 29(-0.25,-2.865) 30(-0.25,2.865) 31(0.25,-2.865) 32(0.25,2.865) 33(0.75,-2.865) 34(0.75,2.865) 35(1.25,-2.865) 36(1.25,2.865) 37(1.75,-2.865) 38(1.75,2.865) 39(2.25,-2.865) 40(2.25,2.865) 41(2.75,-2.865) 42(2.75,2.865) 43(3.25,-2.865) 44(3.25,2.865) 45(3.75,-2.865) 46(3.75,2.865) 47(4.25,-2.865) 48(4.25,2.865) 49(4.75,-2.865) 50(4.75,2.865) 51(5.25,-2.865) 52(5.25,2.865) 53(5.75,-2.865) 54(5.75,2.865) 55(6.25,-2.865) 56(6.25,2.865) 57(6.75,-2.865) 58(6.75,2.865) 59(7.25,-2.865) 60(7.25,2.865)
  rrect23% 2.54x0.43 smd paste+0 mask+0: P1(-8.065,0) P4(8.065,0)
  rrect23% 4.7x0.43 smd paste+0 mask+0: P2(-3.175,0) P3(3.175,0)
  round 1.02 hole 1.02 unplated paste-2539.97 mask+0: ""(-10.065,2.67) ""(10.065,2.67)
  silkscreen extent -10.72,-3.91 10.72,3.68, body extent -10.82,-4.1 10.82,4.1, height 0.25
"FP-RC0402FR-0712KL_0402 (1005 METRIC)-MFG" [mm]
  rrect20% 0.5x0.6 smd paste+0 mask+0: 1(-0.5,0) 2(0.5,0)
  silkscreen extent -0.5,-0.67 0.5,0.67, body extent -0.5,-0.25 0.5,0.25, height 0.4
FP-SPM7054VT-2R2M-D_SMT_IND_7MM5_7MM0-MFG [mm]
  rrect4% 2.85x3.3 smd paste+0 mask+0: 1(-2.975,0) 2(2.975,0)
  silkscreen extent -3.95,-3.7 3.95,3.7, body extent -3.75,-3.5 3.75,3.5, height 5.4
FP-TSM-108-01-L-DV-008-P-TR_HDR15-MFG [mm]
  rrect8% 1.27x3.68 smd paste+0 mask+0: 1(-8.89,-2.475) 2(-8.89,2.475) 3(-6.35,-2.475) 4(-6.35,2.475) 5(-3.81,-2.475) 6(-3.81,2.475) 7(-1.27,-2.475) 9(1.27,-2.475) 10(1.27,2.475) 11(3.81,-2.475) 12(3.81,2.475) 13(6.35,-2.475) 14(6.35,2.475) 15(8.89,-2.475) 16(8.89,2.475)
  silkscreen extent -10.16,-5 10.16,2.61, body extent -10.16,-3.85 10.16,3.85, height 10.16
FP-XGL4030-102MEC_SMD_IND_4MM0_4MM0-MFG [mm]
  rrect10% 0.98x3.4 smd paste+0 mask+0: 1(-1.185,0) 2(1.185,0)
  silkscreen extent -2.15,-2.15 2.15,2.15, body extent -2.25,-2.25 2.25,2.25, height 0.25
MTG_159mil [mil] "159mil Non Plated Hole"
  round 150 hole 159 unplated: 1(0,0)
PW0008A-MFG [mm]
  rrect22% 1.5x0.45 smd paste+0 mask+0: 1(-2.9,0.975) 2(-2.9,0.325) 3(-2.9,-0.325) 4(-2.9,-0.975) 5(2.9,-0.975) 6(2.9,-0.325) 7(2.9,0.325) 8(2.9,0.975)
  silkscreen extent -4.13,-1.55 1.77,1.55, body extent -3.75,-1.8 3.75,1.8, height 0.25
RNR0011A [mm]
  rrect50% 0.25x0.28 on Top Paste: 0(-0.375,1.06) 0(0.375,1.06)
  rrect50% 0.25x0.6 on Top Solder: 0(-0.375,0.9) 0(0.375,0.9)
  rrect50% 0.35x0.92 on Top Paste: 0(-0.35,-0.74) 0(0.35,-0.74)
  rrect50% 1x0.52 on Top Solder: 0(0,0.46)
  rrect50% 1x0.52 on Top Paste: 0(0,0.46)
  rrect40% 0.55x0.25 smd: 1(-1.175,0.75) 2(-1.175,0.25) 3(-1.175,-0.25) 4(-1.175,-0.75) 7(1.175,-0.75) 8(1.175,-0.25) 9(1.175,0.25) 10(1.175,0.75)
  rrect29% 0.45x1.1 smd paste-0.225 mask-0.05: 5(-0.35,-0.7) 6(0.35,-0.7)
  rrect10% 1.1x1.1 smd paste-0.6 mask-0.6: 11(0,0.7)
  silkscreen extent -1.38,-1.15 1.38,1.15, body extent -1.3,-1.05 1.3,1.05, height 1.01
RYT0009A-MFG [mm]
  rrect40% 0.875x0.25 smd paste+0 mask+0: 1(-0.763,0.25) 2(-0.763,-0.25) 5(0.763,-0.25) 6(0.763,0.25)
  round 0.255 smd paste+0 mask+0: 3(-0.509,-0.828)
  round 0.278 smd paste+0 mask+0: 4(0.487,-0.787)
  round 0.26 smd paste+0 mask+0: 7(0.537,0.787)
  rrect40% 0.25x0.65 smd paste+0 mask+0: 8(0,0.95)
  round 0.242 smd paste+0 mask+0: 9(-0.509,0.828)
  Top Layer region: -1.2,-0.825 -1.193,-0.85 -1.175,-0.868 -1.15,-0.875 -1.15,-0.875 -0.675,-0.875 -0.656,-0.879 -0.64,-0.89 -0.629,-0.906 -0.625,-0.925 -0.625,-0.925 -0.625,-1.225 -0.618,-1.25 -0.6,-1.268 -0.575,-1.275 -0.575,-1.275 -0.425,-1.275 -0.406,-1.271 -0.39,-1.26 -0.379,-1.244 -0.375,-1.225 -0.375,-1.225 -0.375,-0.912 -0.368,-0.887 -0.35,-0.868 -0.35,-0.868 -0.337,-0.857 -0.328,-0.842 -0.325,-0.825 -0.325,-0.825 -0.325,-0.675 -0.329,-0.656 -0.34,-0.64 -0.356,-0.629 -0.375,-0.625 -0.375,-0.625 -1.15,-0.625 -1.169,-0.629 -1.185,-0.64 -1.196,-0.656 -1.2,-0.675 -1.2,-0.675
  Top Layer region: 1.2,-0.825 1.193,-0.85 1.175,-0.868 1.15,-0.875 1.15,-0.875 0.675,-0.875 0.656,-0.879 0.64,-0.89 0.629,-0.906 0.625,-0.925 0.625,-0.925 0.625,-1.225 0.618,-1.25 0.6,-1.268 0.575,-1.275 0.575,-1.275 0.425,-1.275 0.406,-1.271 0.39,-1.26 0.379,-1.244 0.375,-1.225 0.375,-1.225 0.375,-0.912 0.372,-0.894 0.363,-0.879 0.35,-0.868 0.35,-0.868 0.337,-0.857 0.328,-0.842 0.325,-0.825 0.325,-0.825 0.325,-0.675 0.329,-0.656 0.34,-0.64 0.356,-0.629 0.375,-0.625 0.375,-0.625 1.15,-0.625 1.169,-0.629 1.185,-0.64 1.196,-0.656 1.2,-0.675 1.2,-0.675
  Top Layer region: 1.2,0.825 1.193,0.85 1.175,0.868 1.15,0.875 1.15,0.875 0.675,0.875 0.656,0.879 0.64,0.89 0.629,0.906 0.625,0.925 0.625,0.925 0.625,1.225 0.618,1.25 0.6,1.268 0.575,1.275 0.575,1.275 0.425,1.275 0.406,1.271 0.39,1.26 0.379,1.244 0.375,1.225 0.375,1.225 0.375,0.675 0.379,0.656 0.39,0.64 0.406,0.629 0.425,0.625 0.425,0.625 1.15,0.625 1.169,0.629 1.185,0.64 1.196,0.656 1.2,0.675 1.2,0.675
  Top Layer region: -1.2,0.825 -1.193,0.85 -1.175,0.868 -1.15,0.875 -1.15,0.875 -0.675,0.875 -0.656,0.879 -0.64,0.89 -0.629,0.906 -0.625,0.925 -0.625,0.925 -0.625,1.225 -0.618,1.25 -0.6,1.268 -0.575,1.275 -0.575,1.275 -0.425,1.275 -0.406,1.271 -0.39,1.26 -0.379,1.244 -0.375,1.225 -0.375,1.225 -0.375,0.675 -0.379,0.656 -0.39,0.64 -0.406,0.629 -0.425,0.625 -0.425,0.625 -1.15,0.625 -1.169,0.629 -1.185,0.64 -1.196,0.656 -1.2,0.675 -1.2,0.675
  silkscreen extent -1.92,-1.68 1.05,1.68, body extent -1.3,-1.38 1.3,1.38, height 0.25
SOIC-8 [mm] "duplicate of SO-8.  SOIC, 8-Leads, Body 5.0x4.0mm (max), Pitch 1.27mm, IPC Medium Density"
  rrect17% 1.45x0.6 smd: 1(-2.725,1.905) 2(-2.725,0.635) 3(-2.725,-0.635) 4(-2.725,-1.905) 5(2.725,-1.905) 6(2.725,-0.635) 7(2.725,0.635) 8(2.725,1.905)
  silkscreen extent -3.5,-2.5 0.9,2.5, body extent -3,-2.45 3,2.45, height 1.63
SW_CAS-D20TA [mm] "SMD, 6-Leads, Body 5.4x3.9mm, Pitch 1.75mm"
  rect 1.6x1 smd: 1(-1.85,1.75) 2(-1.85,0) 3(-1.85,-1.75) 4(1.85,1.75) 5(1.85,0) 6(1.85,-1.75)
  silkscreen extent -1.95,-2.7 1.95,2.9, body extent -2.1,-2.7 2.1,2.7, height 2.5
TESTPOINT [mil]
  round 80 hole 37.99: 1(0,0)
  silkscreen extent -53,-54 53,54
TI_STACKED_OVERLAY_SMALL [mil]
  silkscreen extent -418,-98 418,98
TP_SM_1MM [mm] "1mm Test Point, SMT"
  round 1 smd paste-0.5: 1(0,0)
WEEE_Minimum [mil] "WEEElie bin"
  silkscreen extent -95,-172 99,104
ZEX0256A-MFG [mm]
  round 0.35 smd paste+0 mask+0.05: A1(-6,6) A2(-5.2,6) A3(-4.4,6) A4(-3.6,6) A5(-2.8,6) A6(-2,6) A7(-1.2,6) A8(-0.4,6) A9(0.4,6) A10(1.2,6) A11(2,6) A12(2.8,6) A13(3.6,6) A14(4.4,6) A15(5.2,6) A16(6,6) B1(-6,5.2) B2(-5.2,5.2) B3(-4.4,5.2) B4(-3.6,5.2) B5(-2.8,5.2) B6(-2,5.2) B7(-1.2,5.2) B8(-0.4,5.2) B9(0.4,5.2) B10(1.2,5.2) B11(2,5.2) B12(2.8,5.2) B13(3.6,5.2) B14(4.4,5.2) B15(5.2,5.2) B16(6,5.2) C1(-6,4.4) C2(-5.2,4.4) C3(-4.4,4.4) C4(-3.6,4.4) C5(-2.8,4.4) C6(-2,4.4) C7(-1.2,4.4) C8(-0.4,4.4) C9(0.4,4.4) C10(1.2,4.4) C11(2,4.4) C12(2.8,4.4) C13(3.6,4.4) C14(4.4,4.4) C15(5.2,4.4) C16(6,4.4) D1(-6,3.6) D2(-5.2,3.6) D3(-4.4,3.6) D4(-3.6,3.6) D5(-2.8,3.6) D6(-2,3.6) D7(-1.2,3.6) D8(-0.4,3.6) D9(0.4,3.6) D10(1.2,3.6) D11(2,3.6) D12(2.8,3.6) D13(3.6,3.6) D14(4.4,3.6) D15(5.2,3.6) D16(6,3.6) E1(-6,2.8) E2(-5.2,2.8) E3(-4.4,2.8) E4(-3.6,2.8) E5(-2.8,2.8) E6(-2,2.8) E7(-1.2,2.8) E8(-0.4,2.8) E9(0.4,2.8) E10(1.2,2.8) E11(2,2.8) E12(2.8,2.8) E13(3.6,2.8) E14(4.4,2.8) E15(5.2,2.8) E16(6,2.8) F1(-6,2) F2(-5.2,2) F3(-4.4,2) F4(-3.6,2) F5(-2.8,2) F6(-2,2) F7(-1.2,2) F8(-0.4,2) F9(0.4,2) F10(1.2,2) F11(2,2) F12(2.8,2) F13(3.6,2) F14(4.4,2) F15(5.2,2) F16(6,2) G1(-6,1.2) G2(-5.2,1.2) G3(-4.4,1.2) G4(-3.6,1.2) G5(-2.8,1.2) G6(-2,1.2) G7(-1.2,1.2) G8(-0.4,1.2) G9(0.4,1.2) G10(1.2,1.2) G11(2,1.2) G12(2.8,1.2) G13(3.6,1.2) G14(4.4,1.2) G15(5.2,1.2) G16(6,1.2) H1(-6,0.4) H2(-5.2,0.4) H3(-4.4,0.4) H4(-3.6,0.4) H5(-2.8,0.4) H6(-2,0.4) H7(-1.2,0.4) H8(-0.4,0.4) H9(0.4,0.4) H10(1.2,0.4) H11(2,0.4) H12(2.8,0.4) H13(3.6,0.4) H14(4.4,0.4) H15(5.2,0.4) H16(6,0.4) J1(-6,-0.4) J2(-5.2,-0.4) J3(-4.4,-0.4) J4(-3.6,-0.4) J5(-2.8,-0.4) J6(-2,-0.4) J7(-1.2,-0.4) J8(-0.4,-0.4) J9(0.4,-0.4) J10(1.2,-0.4) J11(2,-0.4) J12(2.8,-0.4) J13(3.6,-0.4) J14(4.4,-0.4) J15(5.2,-0.4) J16(6,-0.4) K1(-6,-1.2) K2(-5.2,-1.2) K3(-4.4,-1.2) K4(-3.6,-1.2) K5(-2.8,-1.2) K6(-2,-1.2) K7(-1.2,-1.2) K8(-0.4,-1.2) K9(0.4,-1.2) K10(1.2,-1.2) K11(2,-1.2) K12(2.8,-1.2) K13(3.6,-1.2) K14(4.4,-1.2) K15(5.2,-1.2) K16(6,-1.2) L1(-6,-2) L2(-5.2,-2) L3(-4.4,-2) L4(-3.6,-2) L5(-2.8,-2) L6(-2,-2) L7(-1.2,-2) L8(-0.4,-2) L9(0.4,-2) L10(1.2,-2) L11(2,-2) L12(2.8,-2) L13(3.6,-2) L14(4.4,-2) L15(5.2,-2) L16(6,-2) M1(-6,-2.8) M2(-5.2,-2.8) M3(-4.4,-2.8) M4(-3.6,-2.8) M5(-2.8,-2.8) M6(-2,-2.8) M7(-1.2,-2.8) M8(-0.4,-2.8) M9(0.4,-2.8) M10(1.2,-2.8) M11(2,-2.8) M12(2.8,-2.8) M13(3.6,-2.8) M14(4.4,-2.8) M15(5.2,-2.8) M16(6,-2.8) N1(-6,-3.6) N2(-5.2,-3.6) N3(-4.4,-3.6) N4(-3.6,-3.6) N5(-2.8,-3.6) N6(-2,-3.6) N7(-1.2,-3.6) N8(-0.4,-3.6) N9(0.4,-3.6) N10(1.2,-3.6) N11(2,-3.6) N12(2.8,-3.6) N13(3.6,-3.6) N14(4.4,-3.6) N15(5.2,-3.6) N16(6,-3.6) P1(-6,-4.4) P2(-5.2,-4.4) P3(-4.4,-4.4) P4(-3.6,-4.4) P5(-2.8,-4.4) P6(-2,-4.4) P7(-1.2,-4.4) P8(-0.4,-4.4) P9(0.4,-4.4) P10(1.2,-4.4) P11(2,-4.4) P12(2.8,-4.4) P13(3.6,-4.4) P14(4.4,-4.4) P15(5.2,-4.4) P16(6,-4.4) R1(-6,-5.2) R2(-5.2,-5.2) R3(-4.4,-5.2) R4(-3.6,-5.2) R5(-2.8,-5.2) R6(-2,-5.2) R7(-1.2,-5.2) R8(-0.4,-5.2) R9(0.4,-5.2) R10(1.2,-5.2) R11(2,-5.2) R12(2.8,-5.2) R13(3.6,-5.2) R14(4.4,-5.2) R15(5.2,-5.2) R16(6,-5.2) T1(-6,-6) T2(-5.2,-6) T3(-4.4,-6) T4(-3.6,-6) T5(-2.8,-6) T6(-2,-6) T7(-1.2,-6) T8(-0.4,-6) T9(0.4,-6) T10(1.2,-6) T11(2,-6) T12(2.8,-6) T13(3.6,-6) T14(4.4,-6) T15(5.2,-6) T16(6,-6)
  silkscreen extent -7.17,-6.55 6.55,6.55, body extent -7.05,-7.05 7.05,7.05, height 0.25

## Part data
C1 C2 C46 C49 C52 C53 C61 C63 C65 C70 C72 C86: library part CMP-0120207-1, "10 µF ±20% 10V Ceramic Capacitor X5R 0402 (1005 Metric)", Manufacturer=Murata, Operating Temperature Range="-55°C to +85°C", TempCo=15%, Temperature Characteristic=X5R, Tolerance_%=20%, ValueDisplayed=10uF
C3 C4 C5 C13 C14 C31 C32 C41 C84 C92: library part CMP-0081010-1, "CAP, CERM, 2.2 µF, 25 V,+/- 20%, X5R, 0402", Cap_Case=0402, Manufacturer=MuRata, Supplier Part Number 1=490-10457-1-ND, TempCo=X5R, Tolerance_%=20%, Value2=25V, ValueDisplayed=2.2µF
